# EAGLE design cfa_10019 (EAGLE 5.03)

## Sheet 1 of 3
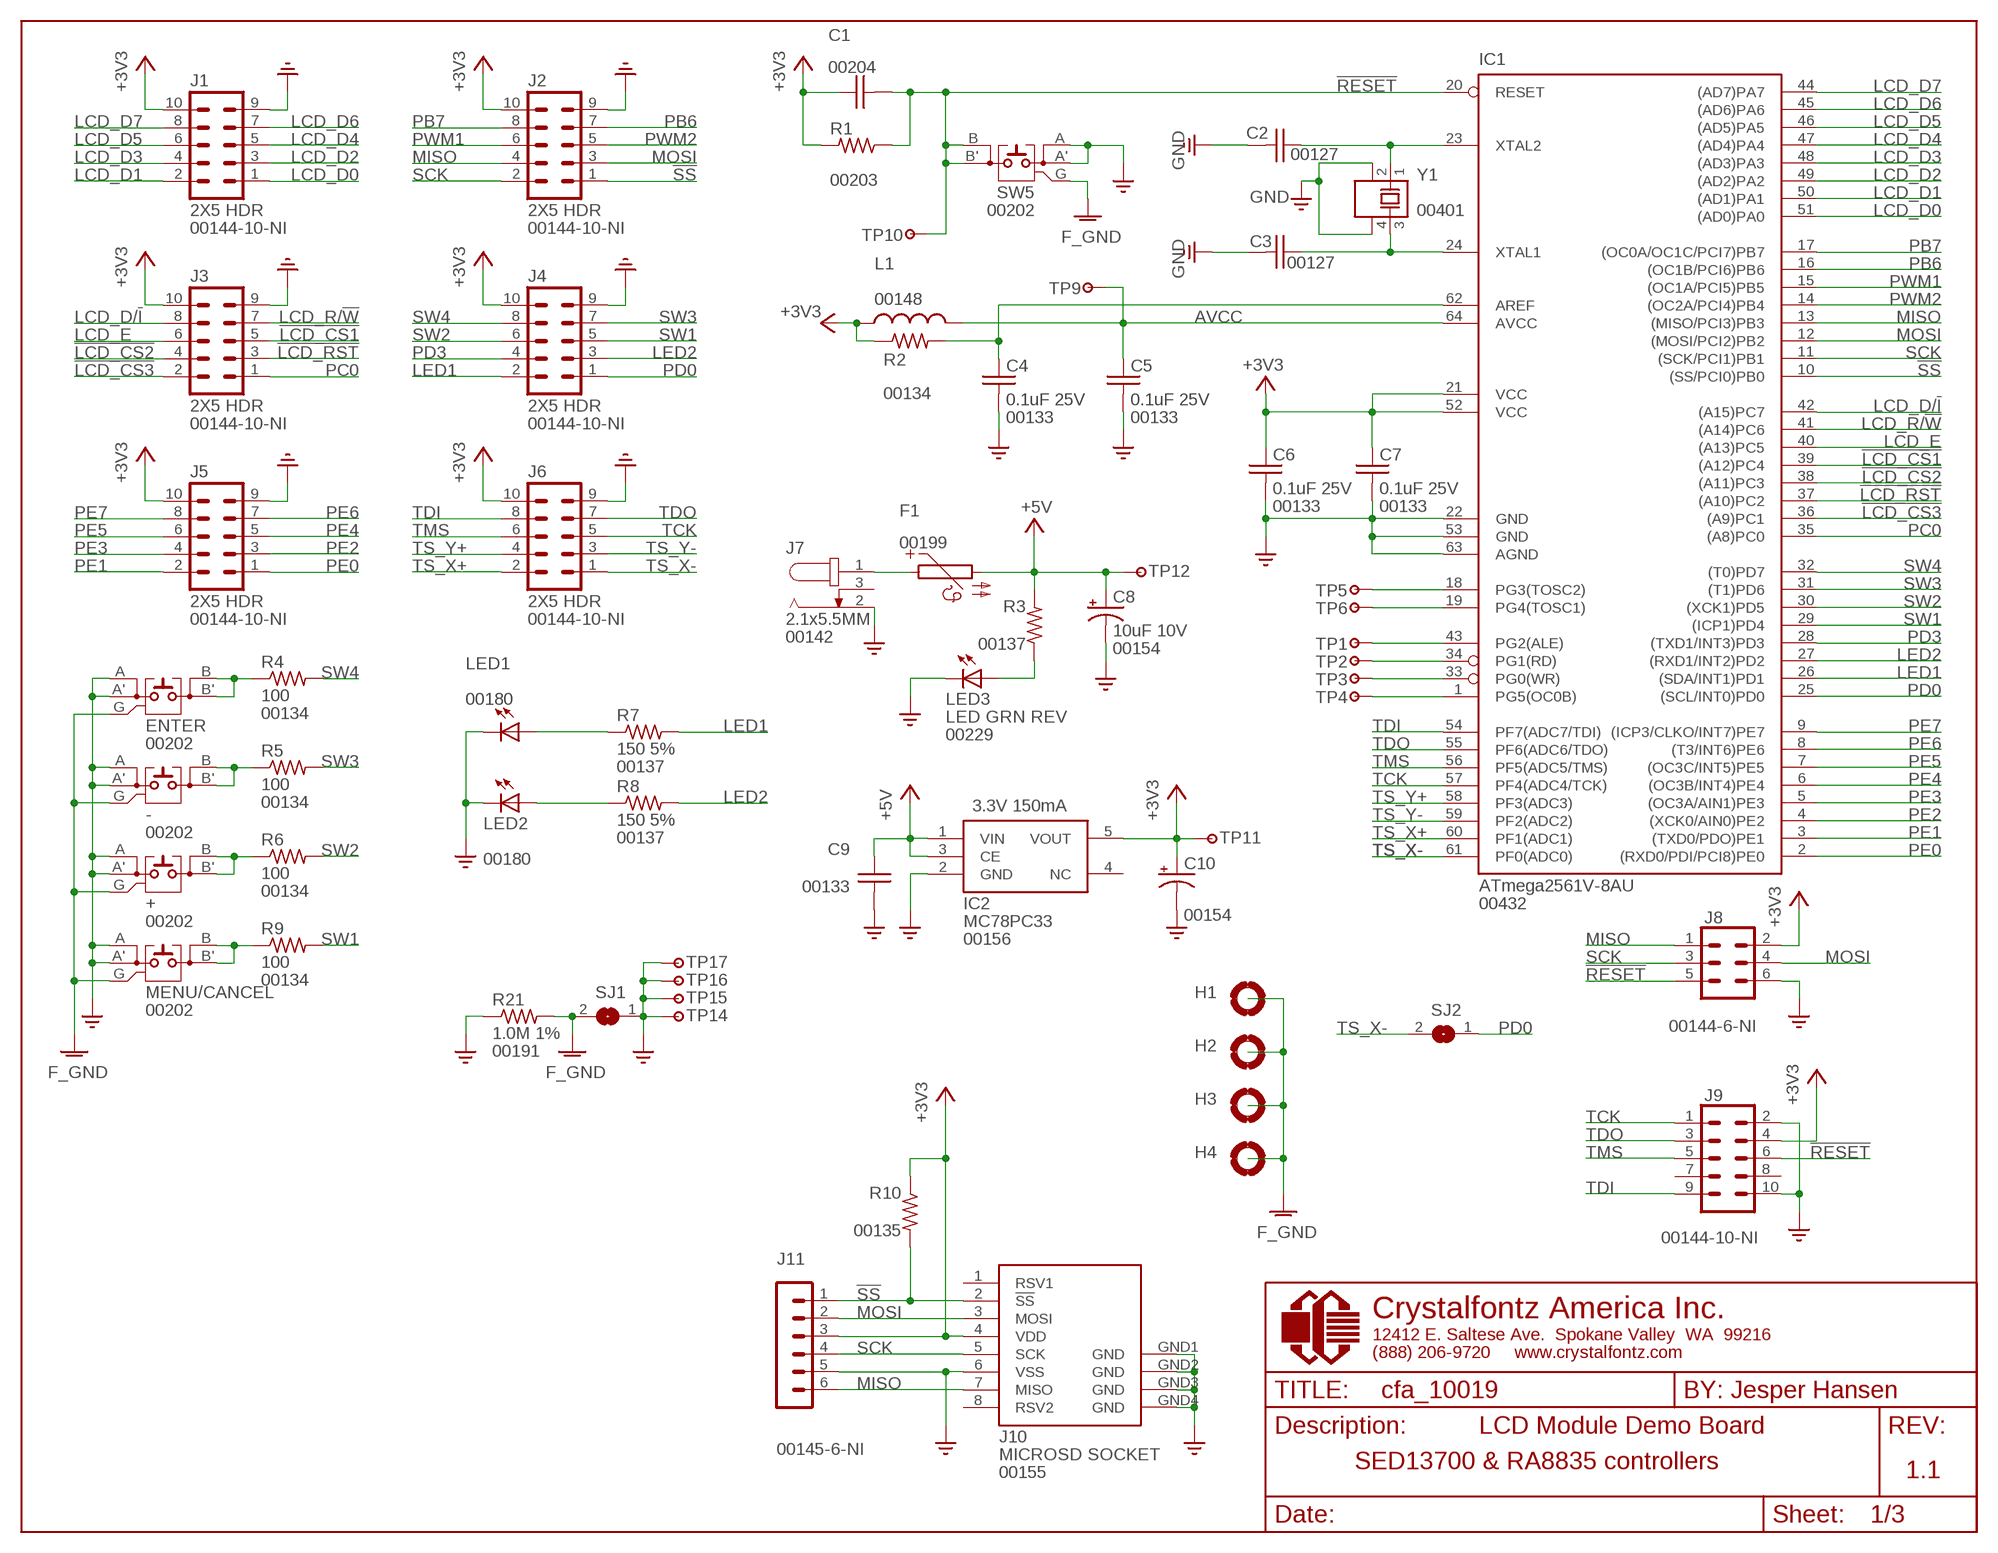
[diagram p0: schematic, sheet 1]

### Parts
+  00202  [EVQPB]
-  00202  [EVQPB]
C1  00204  [CAPC1608X90N]
C2  00127  [CAPC1608X87N]
C3  00127  [CAPC1608X87N]
C4  00133  [CAPC1608X87N]
C5  00133  [CAPC1608X87N]
C6  00133  [CAPC1608X87N]
C7  00133  [CAPC1608X87N]
C8  00154  [CAPMP6032X250N]
C9  00133  [CAPC1608X87N]
C10  00154  [CAPMP6032X250N]
ENTER  00202  [EVQPB]
F1  00199  [RESC3216X85N]
H1  MOUNT-PAD-ROUND3.2  [3,2-PAD]
H2  MOUNT-PAD-ROUND3.2  [3,2-PAD]
H3  MOUNT-PAD-ROUND3.2  [3,2-PAD]
H4  MOUNT-PAD-ROUND3.2  [3,2-PAD]
IC1  00432  [TQFP64-AEB]
IC2  00156  [SOT23-5L]
J1  00144-10-NI  [MA05-2]
J2  00144-10-NI  [MA05-2]
J3  00144-10-NI  [MA05-2]
J4  00144-10-NI  [MA05-2]
J5  00144-10-NI  [MA05-2]
J6  00144-10-NI  [MA05-2]
J7  00142  [PJ-102AH]
J8  00144-6-NI  [MA03-2]
J9  00144-10-NI  [MA05-2]
J10  00155  [3M_MICROSD]
J11  00145-6-NI  [MA06-1]
L1  00148  [R0805]
LED1  00180  [T776_LED_BOTTOM]
LED2  00180  [T776_LED_BOTTOM]
LED3  00229  [T776_LED_BOTTOM]
MENU/CANCEL  00202  [EVQPB]
R1  00203  [RESC1608X50N]
R2  00134  [RESC1608X38N]
R3  00137  [R0603]
R4  00134  [RESC1608X38N]
R5  00134  [RESC1608X38N]
R6  00134  [RESC1608X38N]
R7  00137  [R0603]
R8  00137  [R0603]
R9  00134  [RESC1608X38N]
R10  00135  [RESC1608X38N]
R21  00191  [RESC1608X55N]
SJ1  SJ  [SJ]
SJ2  SJ  [SJ]
SW5  00202  [EVQPB]
TP1  TP-VIA-3.2MM  [VIA-3.2MM-HOLE]
TP2  TP-VIA-3.2MM  [VIA-3.2MM-HOLE]
TP3  TP-VIA-3.2MM  [VIA-3.2MM-HOLE]
TP4  TP-VIA-3.2MM  [VIA-3.2MM-HOLE]
TP5  TP-VIA-3.2MM  [VIA-3.2MM-HOLE]
TP6  TP-VIA-3.2MM  [VIA-3.2MM-HOLE]
TP9  TP-VIA-1.0MM  [VIA-1MM-HOLE]
TP10  TP-VIA-1.0MM  [VIA-1MM-HOLE]
TP11  TP-VIA-1.0MM  [VIA-1MM-HOLE]
TP12  TP-VIA-1.0MM  [VIA-1MM-HOLE]
TP14  TP-VIA-1.0MM  [VIA-1MM-HOLE]
TP15  TP-VIA-1.0MM  [VIA-1MM-HOLE]
TP16  TP-VIA-1.0MM  [VIA-1MM-HOLE]
TP17  TP-VIA-1.0MM  [VIA-1MM-HOLE]
Y1  00401  [ABM3B]

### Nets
!LCD_CS1: IC1.39((A12)PC4) J3.5 ; also sheet 2
!LCD_CS2: IC1.38((A11)PC3) J3.4
!LCD_CS3: IC1.36((A9)PC1) J3.2
!LCD_RST: IC1.37((A10)PC2) J3.3 ; also sheet 2
!RESET: C1.2 IC1.20(RESET) J8.5 J9.6 R1.1 SW5.B SW5.B' TP10.1
!SS: IC1.10((SS/PCI0)PB0) J2.1 J10.2(!SS) J11.1 R10.2
+3V3: C1.1 C6.1 C7.1 C10.1(+) IC1.21(VCC) IC1.52(VCC) IC2.5(VOUT) J1.10 J2.10 J3.10 J4.10 J5.10 J6.10 J8.2 J9.4 J10.4(VDD) J11.3 L1.1 R1.2 R2.1 R10.1 TP11.1 ; also sheet 2
+5V: C8.1(+) C9.1 F1.2 IC2.1(VIN) IC2.3(CE) R3.2 TP12.1 ; also sheet 2
AVCC: C5.1 IC1.64(AVCC) L1.2 TP9.1
FOO: +.A +.A' -.A -.A' C2.2 C3.2 C4.2 C5.2 C6.2 C7.2 C8.2(-) C9.2 C10.2(-) ENTER.A ENTER.A' IC1.22(GND) IC1.53(GND) IC1.63(AGND) IC2.2(GND) J1.9 J2.9 J3.9 J4.9 J5.9 J6.9 J7.2 J8.6 J9.2 J9.10 J10.6(VSS) J10.GND1(GND) J10.GND2(GND) J10.GND3(GND) J10.GND4(GND) J11.5 LED1.K(C) LED2.K(C) LED3.K(C) MENU/CANCEL.A MENU/CANCEL.A' R21.1 SJ1.1 SW5.A SW5.A' TP14.1 TP15.1 TP16.1 TP17.1 Y1.2(GND) Y1.4(GND) ; supply symbol labelled GND ; also sheet 2
GNDA: +.G -.G ENTER.G H1.B3,2(MOUNT) H2.B3,2(MOUNT) H3.B3,2(MOUNT) H4.B3,2(MOUNT) MENU/CANCEL.G R21.2 SJ1.2 SW5.G ; supply symbol labelled F_GND
LCD_D0: IC1.51((AD0)PA0) J1.1 ; also sheet 2
LCD_D1: IC1.50((AD1)PA1) J1.2 ; also sheet 2
LCD_D2: IC1.49((AD2)PA2) J1.3 ; also sheet 2
LCD_D3: IC1.48((AD3)PA3) J1.4 ; also sheet 2
LCD_D4: IC1.47((AD4)PA4) J1.5 ; also sheet 2
LCD_D5: IC1.46((AD5)PA5) J1.6 ; also sheet 2
LCD_D6: IC1.45((AD6)PA6) J1.7 ; also sheet 2
LCD_D7: IC1.44((AD7)PA7) J1.8 ; also sheet 2
LCD_D/!I: IC1.42((A15)PC7) J3.8 ; also sheet 2
LCD_E: IC1.40((A13)PC5) J3.6 ; also sheet 2
LCD_R/!W: IC1.41((A14)PC6) J3.7 ; also sheet 2
LED1: IC1.26((SDA/INT1)PD1) J4.2 R7.2
LED2: IC1.27((RXD1/INT2)PD2) J4.3 R8.2
MISO: IC1.13((MISO/PCI3)PB3) J2.4 J8.1 J10.7(MISO) J11.6
MOSI: IC1.12((MOSI/PCI2)PB2) J2.3 J8.4 J10.3(MOSI) J11.2
N$1: C2.1 IC1.23(XTAL2) Y1.1
N$2: ENTER.B ENTER.B' R4.1
N$3: C3.1 IC1.24(XTAL1) Y1.3
N$4: -.B -.B' R5.1
N$5: IC1.19(PG4(TOSC1)) TP6.1
N$6: +.B +.B' R6.1
N$7: LED1.A R7.1
N$8: MENU/CANCEL.B MENU/CANCEL.B' R9.1
N$9: C4.1 IC1.62(AREF) R2.2
N$10: LED2.A R8.1
N$11: IC1.43(PG2(ALE)) TP1.1
N$13: IC1.34(PG1(RD)) TP2.1
N$14: F1.1 J7.1
N$15: IC1.33(PG0(WR)) TP3.1
N$17: LED3.A R3.1
N$18: IC1.18(PG3(TOSC2)) TP5.1
N$19: IC1.1(PG5(OC0B)) TP4.1
PB6: IC1.16((OC1B/PCI6)PB6) J2.7
PB7: IC1.17((OC0A/OC1C/PCI7)PB7) J2.8
PC0: IC1.35((A8)PC0) J3.1
PD0: IC1.25((SCL/INT0)PD0) J4.1 SJ2.1
PD3: IC1.28((TXD1/INT3)PD3) J4.4
PE0: IC1.2((RXD0/PDI/PCI8)PE0) J5.1
PE1: IC1.3((TXD0/PDO)PE1) J5.2
PE2: IC1.4((XCK0/AIN0)PE2) J5.3
PE3: IC1.5((OC3A/AIN1)PE3) J5.4
PE4: IC1.6((OC3B/INT4)PE4) J5.5
PE5: IC1.7((OC3C/INT5)PE5) J5.6
PE6: IC1.8((T3/INT6)PE6) J5.7
PE7: IC1.9((ICP3/CLKO/INT7)PE7) J5.8
PWM1: IC1.15((OC1A/PCI5)PB5) J2.6 ; also sheet 2
PWM2: IC1.14((OC2A/PCI4)PB4) J2.5 ; also sheet 2
SCK: IC1.11((SCK/PCI1)PB1) J2.2 J8.3 J10.5(SCK) J11.4
SW1: IC1.29((ICP1)PD4) J4.5 R9.2
SW2: IC1.30((XCK1)PD5) J4.6 R6.2
SW3: IC1.31((T1)PD6) J4.7 R5.2
SW4: IC1.32((T0)PD7) J4.8 R4.2
TCK: IC1.57(PF4(ADC4/TCK)) J6.5 J9.1
TDI: IC1.54(PF7(ADC7/TDI)) J6.8 J9.9
TDO: IC1.55(PF6(ADC6/TDO)) J6.7 J9.3
TMS: IC1.56(PF5(ADC5/TMS)) J6.6 J9.5
TS_X+: IC1.60(PF1(ADC1)) J6.2 ; also sheet 2
TS_X-: IC1.61(PF0(ADC0)) J6.1 SJ2.2 ; also sheet 2
TS_Y+: IC1.58(PF3(ADC3)) J6.4 ; also sheet 2
TS_Y-: IC1.59(PF2(ADC2)) J6.3 ; also sheet 2
Unconnected: IC2.4(NC) J7.3 J9.7 J9.8 J10.1(RSV1) J10.8(RSV2)

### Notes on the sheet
- 3.3V 150mA
- LCD Module Demo Board
- SED13700 & RA8835 controllers
- 1.1

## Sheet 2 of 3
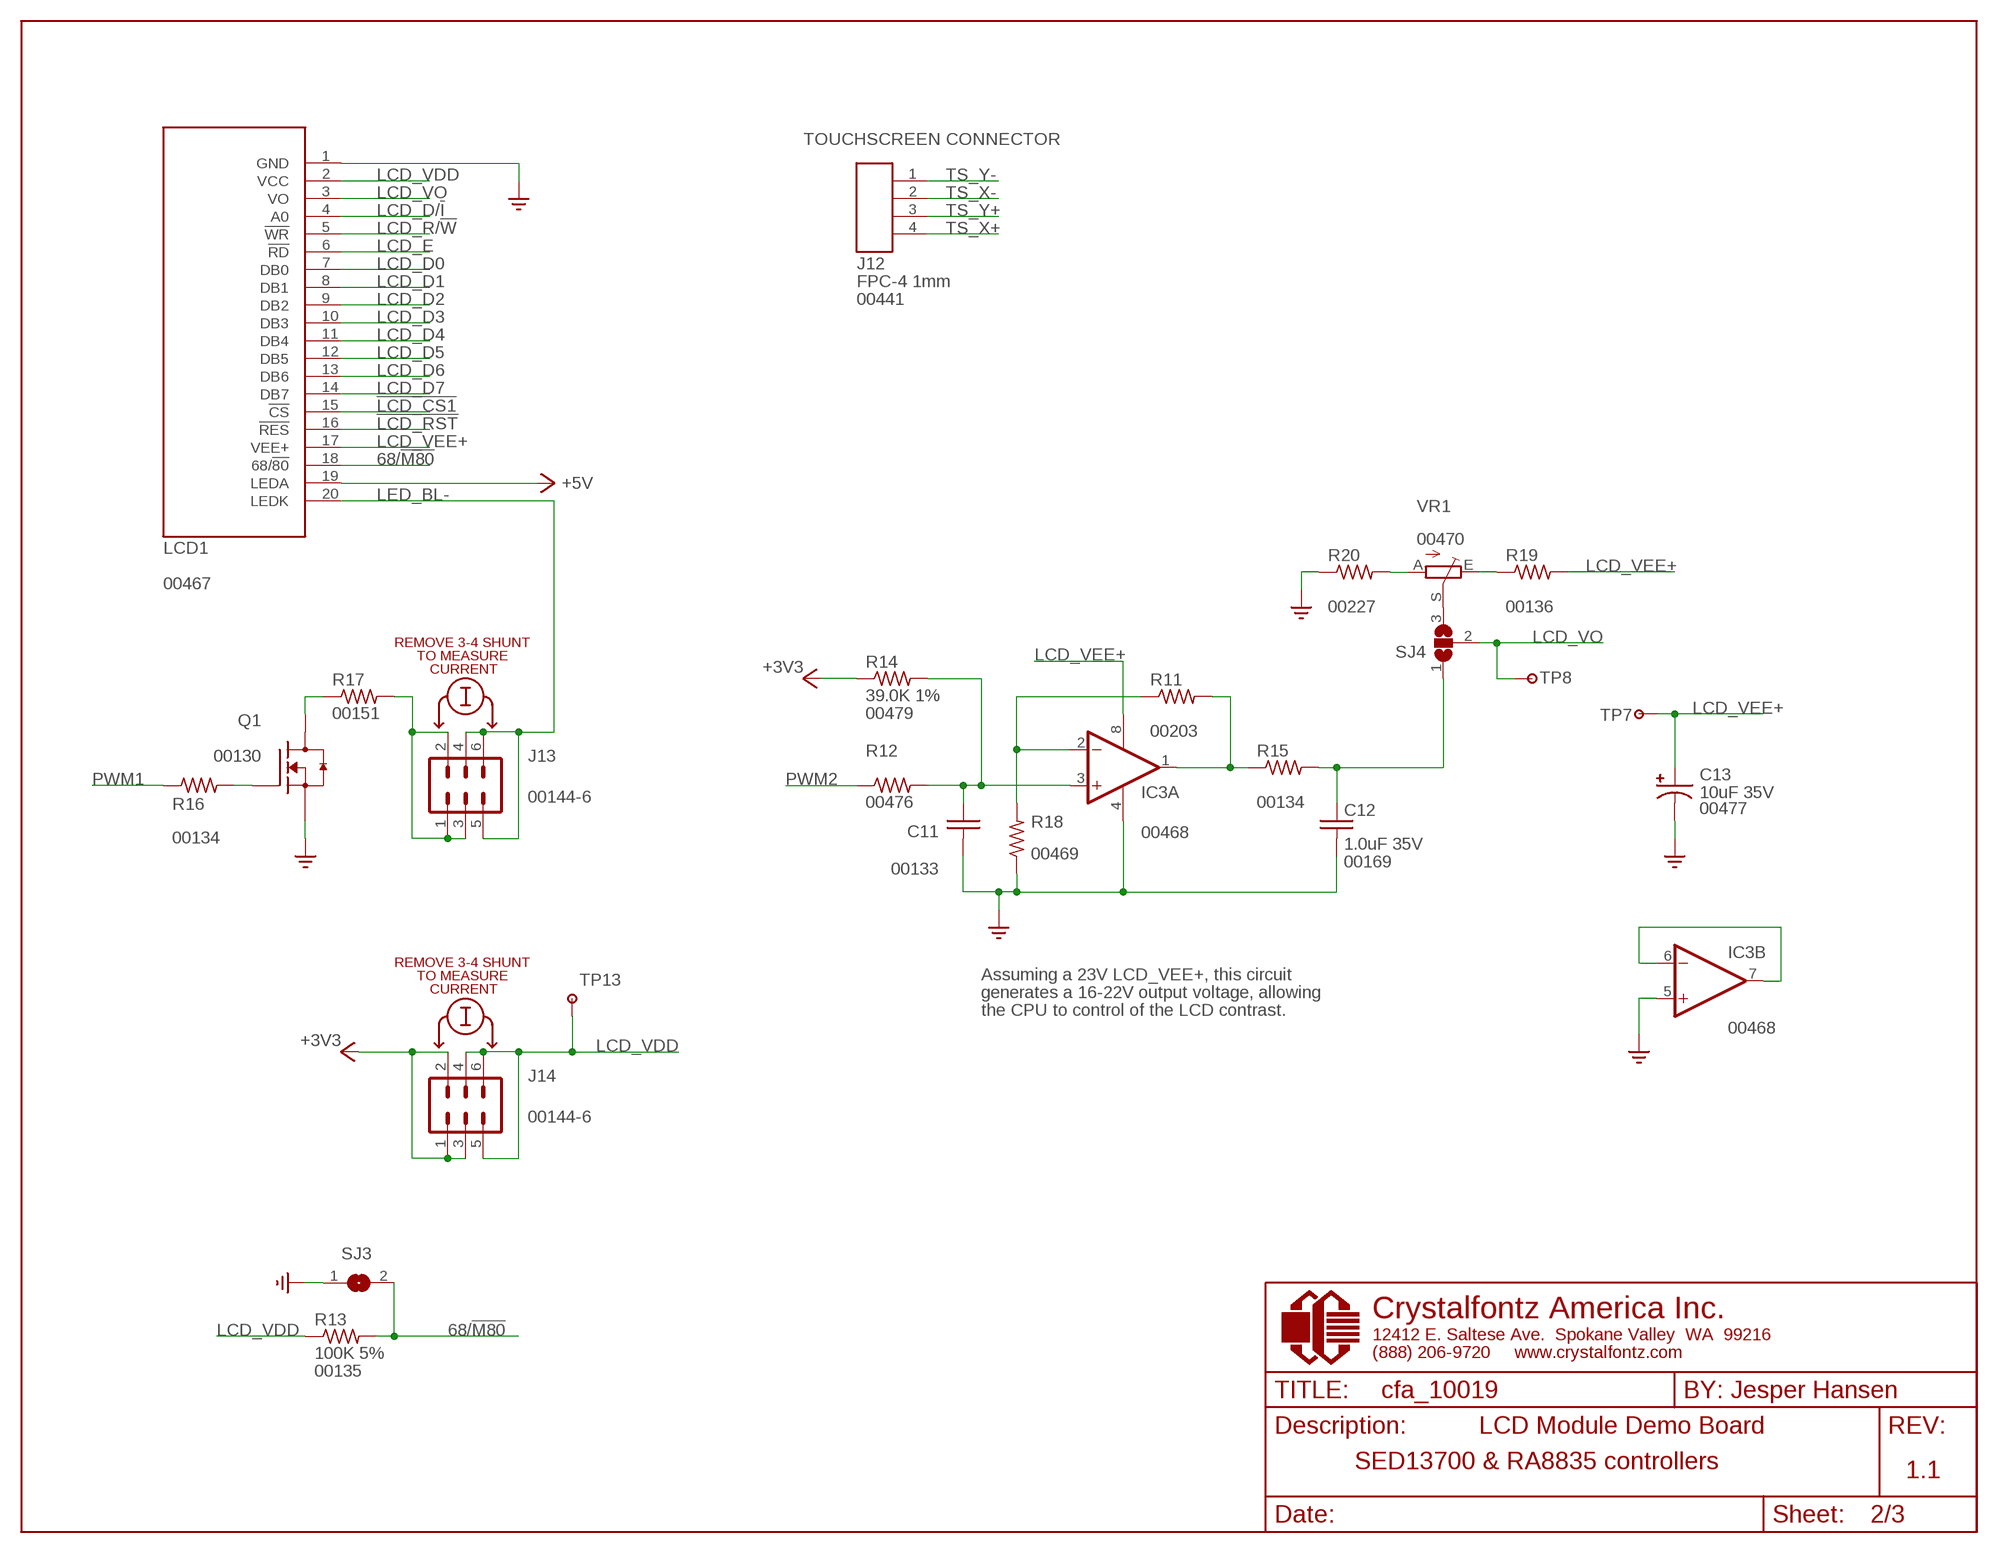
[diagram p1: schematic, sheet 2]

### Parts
C11  00133  [CAPC1608X87N]
C12  00169  [CAPC2012X125N]
C13  00477  [CAPMP6032X250N]
IC3  00468  [SO08]
J12  00441  [52207-0485]
J13  00144-6  [MA03-2]
J14  00144-6  [MA03-2]
LCD1  00467  [CFAX320240]
Q1  00130  [SOT23]
R11  00203  [RESC1608X50N]
R12  00476  [RESC1608X55N]
R13  00135  [RESC1608X38N]
R14  00479  [RESC1608X55N]
R15  00134  [RESC1608X38N]
R16  00134  [RESC1608X38N]
R17  00151  [R2010]
R18  00469  [RESC1608X55N]
R19  00136  [R0603]
R20  00227  [RESC1608X38N]
SJ3  SJ  [SJ]
SJ4  SJ2W  [SJ_2]
TP7  TP-VIA-1.0MM  [VIA-1MM-HOLE]
TP8  TP-VIA-1.0MM  [VIA-1MM-HOLE]
TP13  TP-VIA-1.0MM  [VIA-1MM-HOLE]
VR1  00470  [S63P]

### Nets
68/!M80: LCD1.18(68/!80) R13.2 SJ3.2
!LCD_CS1: LCD1.15(!CS) ; also sheet 1
!LCD_RST: LCD1.16(!RES) ; also sheet 1
+3V3: J14.1 J14.2 J14.3 R14.1 ; also sheet 1
+5V: LCD1.19(LEDA) ; also sheet 1
FOO: C11.2 C12.2 C13.2(-) IC3.4(A:V-) IC3.5(B:+IN) LCD1.1(GND) Q1.2(S) R18.1 R20.1 SJ3.1 ; supply symbol labelled GND ; also sheet 1
LCD_D0: LCD1.7(DB0) ; also sheet 1
LCD_D1: LCD1.8(DB1) ; also sheet 1
LCD_D2: LCD1.9(DB2) ; also sheet 1
LCD_D3: LCD1.10(DB3) ; also sheet 1
LCD_D4: LCD1.11(DB4) ; also sheet 1
LCD_D5: LCD1.12(DB5) ; also sheet 1
LCD_D6: LCD1.13(DB6) ; also sheet 1
LCD_D7: LCD1.14(DB7) ; also sheet 1
LCD_D/!I: LCD1.4(A0) ; also sheet 1
LCD_E: LCD1.6(!RD) ; also sheet 1
LCD_R/!W: LCD1.5(!WR) ; also sheet 1
LCD_VDD: J14.4 J14.5 J14.6 LCD1.2(VCC) R13.1 TP13.1
LCD_VEE+: C13.1(+) IC3.8(A:V+) LCD1.17(VEE+) R19.2 TP7.1
LCD_VO: LCD1.3(VO) SJ4.2 TP8.1
LED_BL-: J13.4 J13.5 J13.6 LCD1.20(LEDK)
N$12: IC3.2(A:-IN) R11.1 R18.2
N$16: IC3.1(A:OUT) R11.2 R15.1
N$20: IC3.6(B:-IN) IC3.7(B:OUT)
N$22: SJ4.3 VR1.S
N$23: C11.1 IC3.3(A:+IN) R12.2 R14.2
N$24: R20.2 VR1.A
N$25: J13.1 J13.2 J13.3 R17.2
N$26: R19.1 VR1.E
N$27: C12.1 R15.2 SJ4.1
N$30: Q1.3(D) R17.1
N$31: Q1.1(G) R16.2
PWM1: R16.1 ; also sheet 1
PWM2: R12.1 ; also sheet 1
TS_X+: J12.4 ; also sheet 1
TS_X-: J12.2 ; also sheet 1
TS_Y+: J12.3 ; also sheet 1
TS_Y-: J12.1 ; also sheet 1

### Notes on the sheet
- TOUCHSCREEN CONNECTOR
- REMOVE 3-4 SHUNT
- TO MEASURE
- CURRENT
- REMOVE 3-4 SHUNT
- TO MEASURE | Assuming a 23V LCD_VEE+, this circuit
- CURRENT
- generates a 16-22V output voltage, allowing
- the CPU to control of the LCD contrast.
- LCD Module Demo Board
- SED13700 & RA8835 controllers
- 1.1

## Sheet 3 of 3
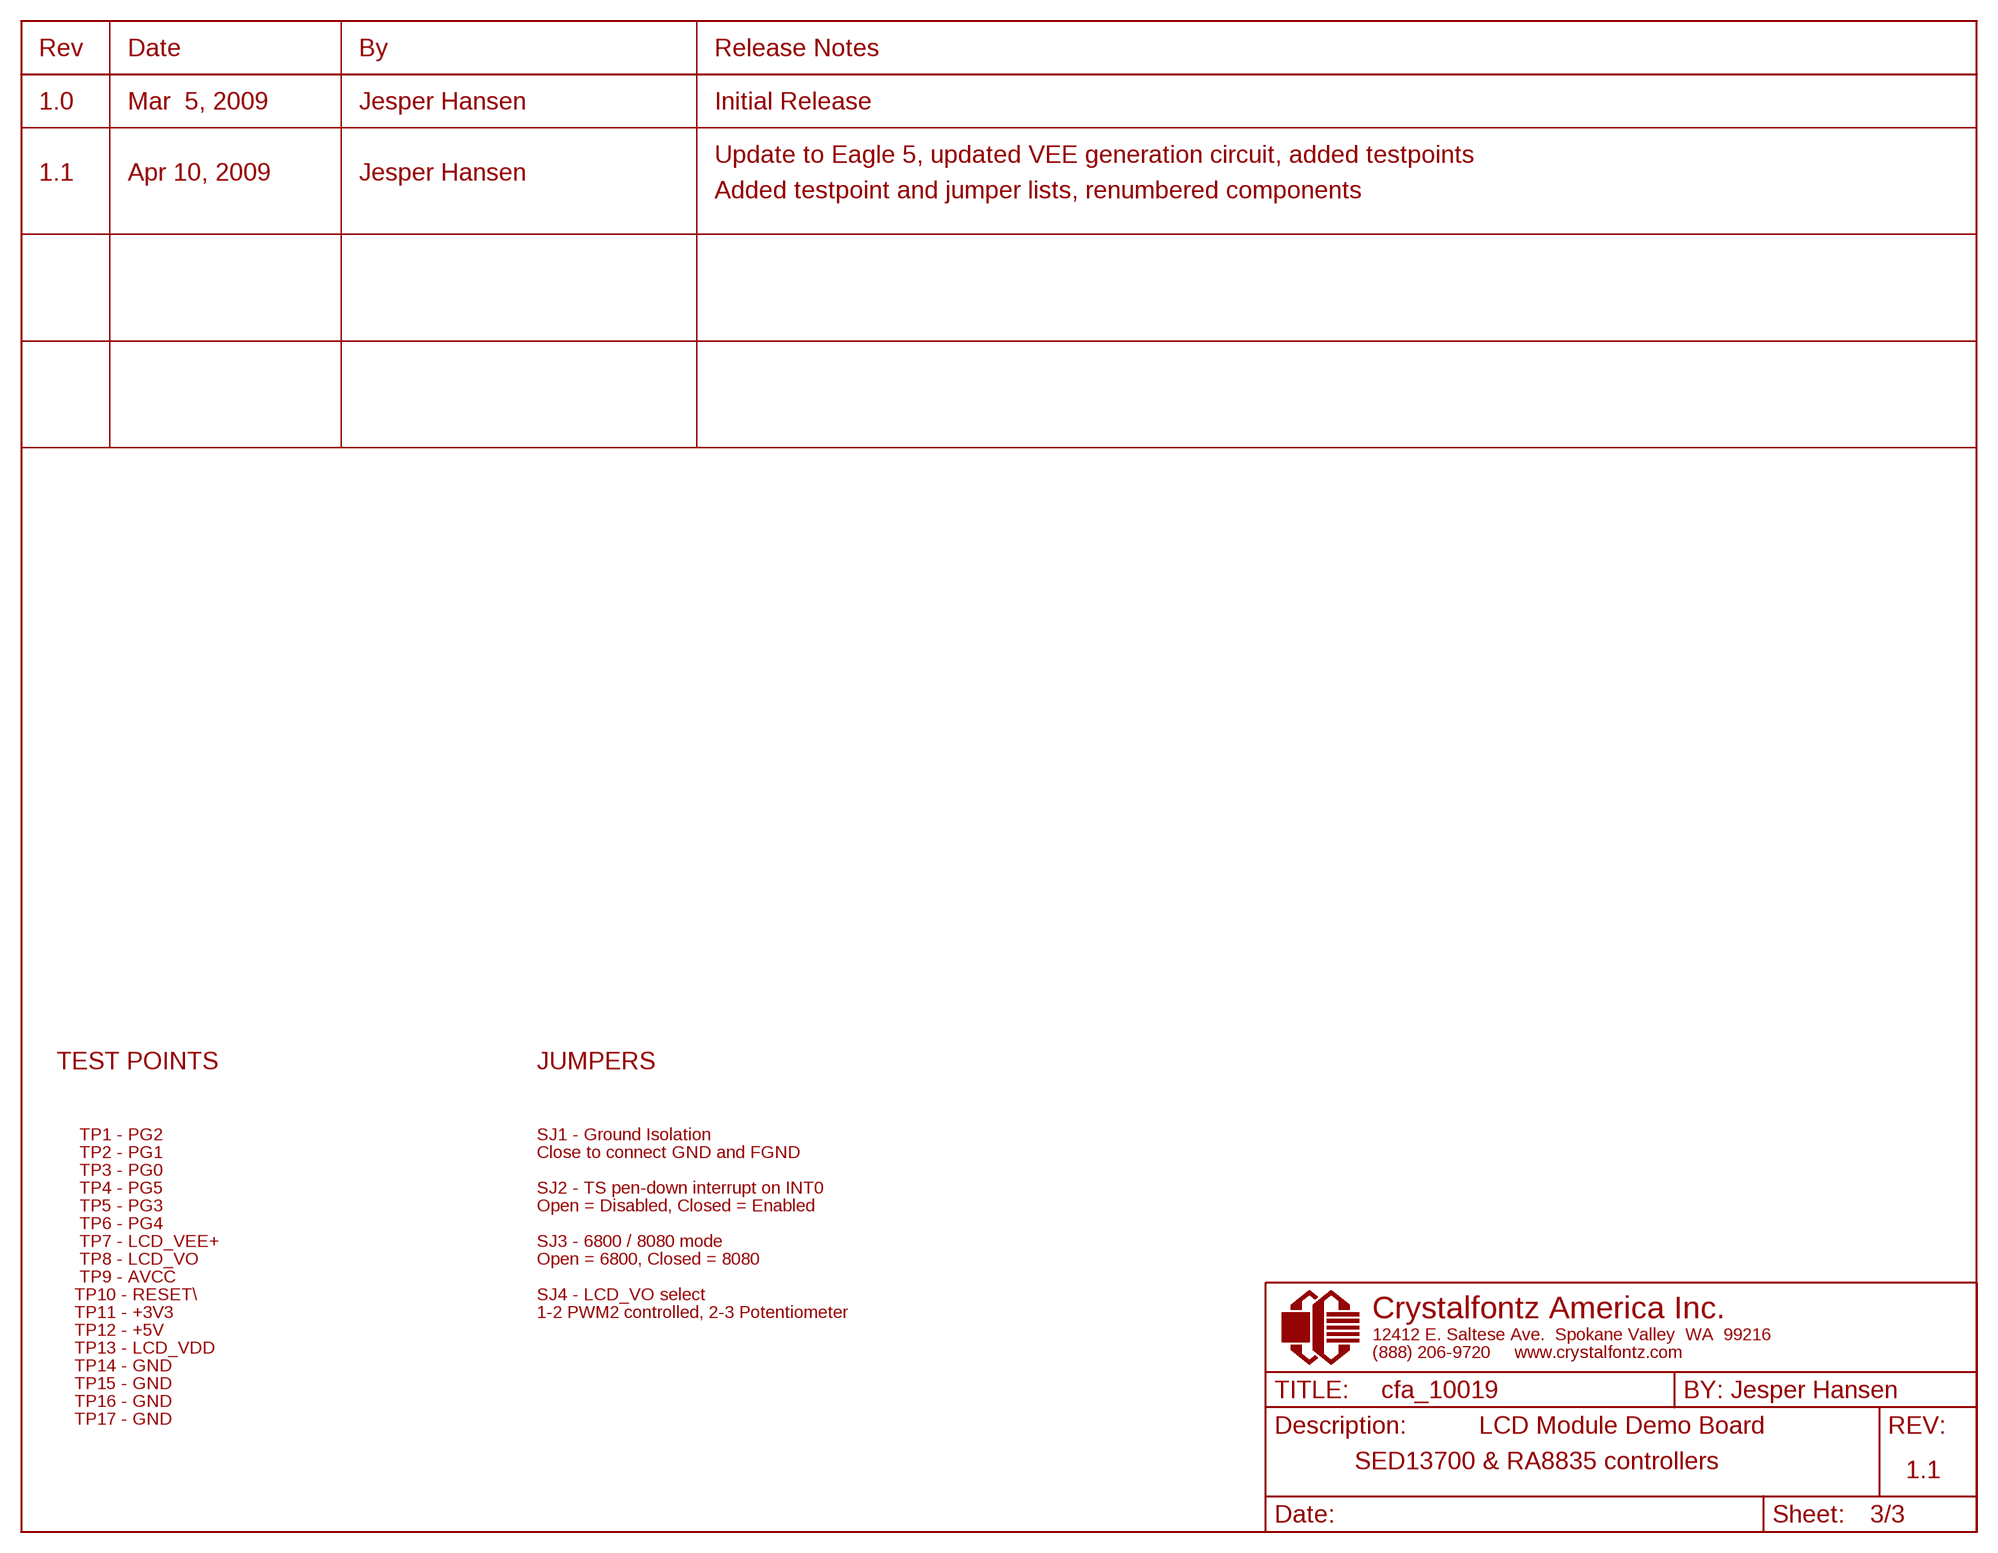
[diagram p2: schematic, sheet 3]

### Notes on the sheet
- Rev | Date | By | Release Notes
- 1.0 | Mar  5, 2009 | Jesper Hansen | Initial Release
- Update to Eagle 5, updated VEE generation circuit, added testpoints
- 1.1 | Apr 10, 2009 | Jesper Hansen
- Added testpoint and jumper lists, renumbered components
- TEST POINTS | JUMPERS
- TP1 - PG2 | SJ1 - Ground Isolation
- TP2 - PG1 | Close to connect GND and FGND
- TP3 - PG0
- TP4 - PG5 | SJ2 - TS pen-down interrupt on INT0
- TP5 - PG3 | Open = Disabled, Closed = Enabled
- TP6 - PG4
- TP7 - LCD_VEE+ | SJ3 - 6800 / 8080 mode
- TP8 - LCD_VO | Open = 6800, Closed = 8080
- TP9 - AVCC
- TP10 - RESET\\ | SJ4 - LCD_VO select
- TP11 - +3V3 | 1-2 PWM2 controlled, 2-3 Potentiometer
- TP12 - +5V
- TP13 - LCD_VDD
- TP14 - GND
- TP15 - GND
- TP16 - GND
- TP17 - GND
- LCD Module Demo Board
- SED13700 & RA8835 controllers
- 1.1

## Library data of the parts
+ - ENTER MENU/CANCEL SW5 = proddev_lib:00202: SPST MOM W/GND, 6MM LIGHT TOUCH SW W/GND H=7 TH; DESC: SPST MOM W/GND
C1 = proddev_lib:00204: 0.22uF 10V, CAP .22UF 10V CERAMIC X5R 0603; DESC: 0.22uF 10V
C2 C3 = proddev_lib:00127: 20pF, CAP CER 20PF 50V 5% C0G 0603; DESC: 20pF
C4-C7 C9 C11 = proddev_lib:00133: 0.1uF 25V, CAP .1UF 25V CERAMIC X7R 0603; DESC: 0.1uF 25V
C8 C10 = proddev_lib:00154: 10uF 10V, CAP TANT 10UF 10V 10% LOESR SMD; DESC: 10uF 10V
C12 = proddev_lib:00169: 1.0UF 35V, CAP CER 1.0UF 35V X7R 0805; DESC: 1.0uF 35V
C13 = proddev_lib2:00477: 10uF 35V,CAP TANTALUM 10UF 35V 20% SMD; DESC: 10uF 35V
F1 = proddev_lib:00199: 500mA, PTC RESETTABLE .50A 13.2V 1206; DESC: 500mA PTC
H1-H4 = holes:MOUNT-PAD-ROUND: MOUNTING PAD, round
IC1 = proddev_lib2:00432: ATmega2561V-8AU, IC AVR MCU 256K 8MHZ LOW-VOLTAGE 64TQFP 256 Kbytes FLASH 8 Kbytes SRAM 4 Kbytes EEPROM DUAL USART 8-channel 10 bit ADC; DESC: ATmega2561V-8AU
IC2 = proddev_lib:00156: MC78PC33, IC REG LDO 150MA 3.3V LN SOT23-5; DESC: MC78PC33
IC3 = proddev_lib2:00468: LT1490 Dual/Quad Over-The-Top Micropower Rail-to-Rail Input and Output Op Amps; DESC: LT1490
J1-J6 J9 = proddev_lib:00144-10-NI: 2X5 HDR, CONN HDR BRKWAY .100 VERT; DESC: 2X5 HDR
J7 = proddev_lib:00142: 2.1x5.5MM, CONN PWR JACK 2.1X5.5MM HIGH CUR; DESC: 2.1x5.5MM
J8 = proddev_lib:00144-6-NI: 2X3 HDR, CONN HDR BRKWAY .100 VERT; DESC: 2X3 HDR
J10 = proddev_lib:00155: MICROSD SOCKET, CONN EJECT MICROSD PUSH-PUSH SMD; DESC: MICROSD SOCKET
J11 = proddev_lib:00145-6-NI: 1X6 HDR, CONN HDR BRKWAY .100 VERT; DESC: 1X6 HDR
J12 = proddev_lib2:00441: CONN FFC/FPC 4POS 1MM R/A SMD, TOP CONTACTS; DESC: FPC-4 1mm
J13 J14 = proddev_lib:00144-6: 2X3 HDR, CONN HDR BRKWAY .100 VERT; DESC: 2X3 HDR
L1 = proddev_lib:00148: 10uH, FERRITE CHIP 1000 OHM 200MA 0805; DESC: 10uH FC
LCD1 = proddev_lib2:00467: Crystalfontz CFAX320240 series Size 95 x 70 mm; DESC: CFAX320240
LED1 LED2 = proddev_lib:00180: LST776, LED SUP RED REV GULWNG 645NM SMD; DESC: LST776 RED
LED3 = proddev_lib:00229: LED GRN, LED PURE GRN REV GLWNG 562NM SMD; DESC: LED GRN REV
Q1 = proddev_lib:00130: IRLML2402, MOSFET N-CH 20V 1.2A SOT-23; DESC: IRLML2402
R1 R11 = proddev_lib:00203: 47K 1/10W 5%, RES 47K OHM 1/10W 5% 0603 SMD; DESC: 47K 5%
R2 R4-R6 R9 R15 R16 = proddev_lib:00134: 100, RES 100 OHM 1/10W 5% 0603 SMD; DESC: 100
R3 R7 R8 = proddev_lib:00137: 150, RES 150 OHM 1/10W 5% 0603 SMD; DESC: 150 5%
R10 R13 = proddev_lib:00135: 100K, RES 100K OHM 1/10W 5% 0603 SMD; DESC: 100K 5%
R12 = proddev_lib2:00476: 15.0K 1/10W 1%,RES 15.0K OHM 1/10W 1% 0603 SMD; DESC: 15k 1%
R14 = proddev_lib2:00479: 39.0K 1%,RES 39.0K OHM 1/10W 1% 0603 SMD; DESC: 39.0K 1%
R17 = proddev_lib:00151: R 1/2W 2010, BACKLIGHT RES 1/2W 2010 SMD; DESC: R 1/2W 2010
R18 = proddev_lib2:00469: RES 8.20K OHM 1/10W 1% 0603 SMD; DESC: 8.2k 1%
R19 = proddev_lib:00136: 1K, RES 1.0K OHM 1/10W 5% 0603 SMD; DESC: 1K 5%
R20 = proddev_lib:00227: 22K, RES 22K OHM 1/10W 5% 0603 SMD; DESC: 22K 5%
R21 = proddev_lib:00191: 1.0M 1/10W 1%, RES 1.00M OHM 1/10W 1% 0603 SMD; DESC: 1.0M 1%
SJ1-SJ3 = proddev_lib:SJ: SMD solder JUMPER
SJ4 = proddev_lib:SJ2W: SMD solder JUMPER
TP1-TP6 = proddev_lib:TP-VIA-3.2MM: 3.2MM Hole Via TP
TP7-TP17 = proddev_lib:TP-VIA-1.0MM: TP 1MM HOLE
VR1 = proddev_lib2:00470: Single Turn Trimmer 3/8 SQ 10Kohms 10% Cermet; DESC: 10k 10%
Y1 = proddev_lib2:00401: Crystal; ABM3B Ceramic SMD Crystal, 5x3.2mm; DESC: 8MHz

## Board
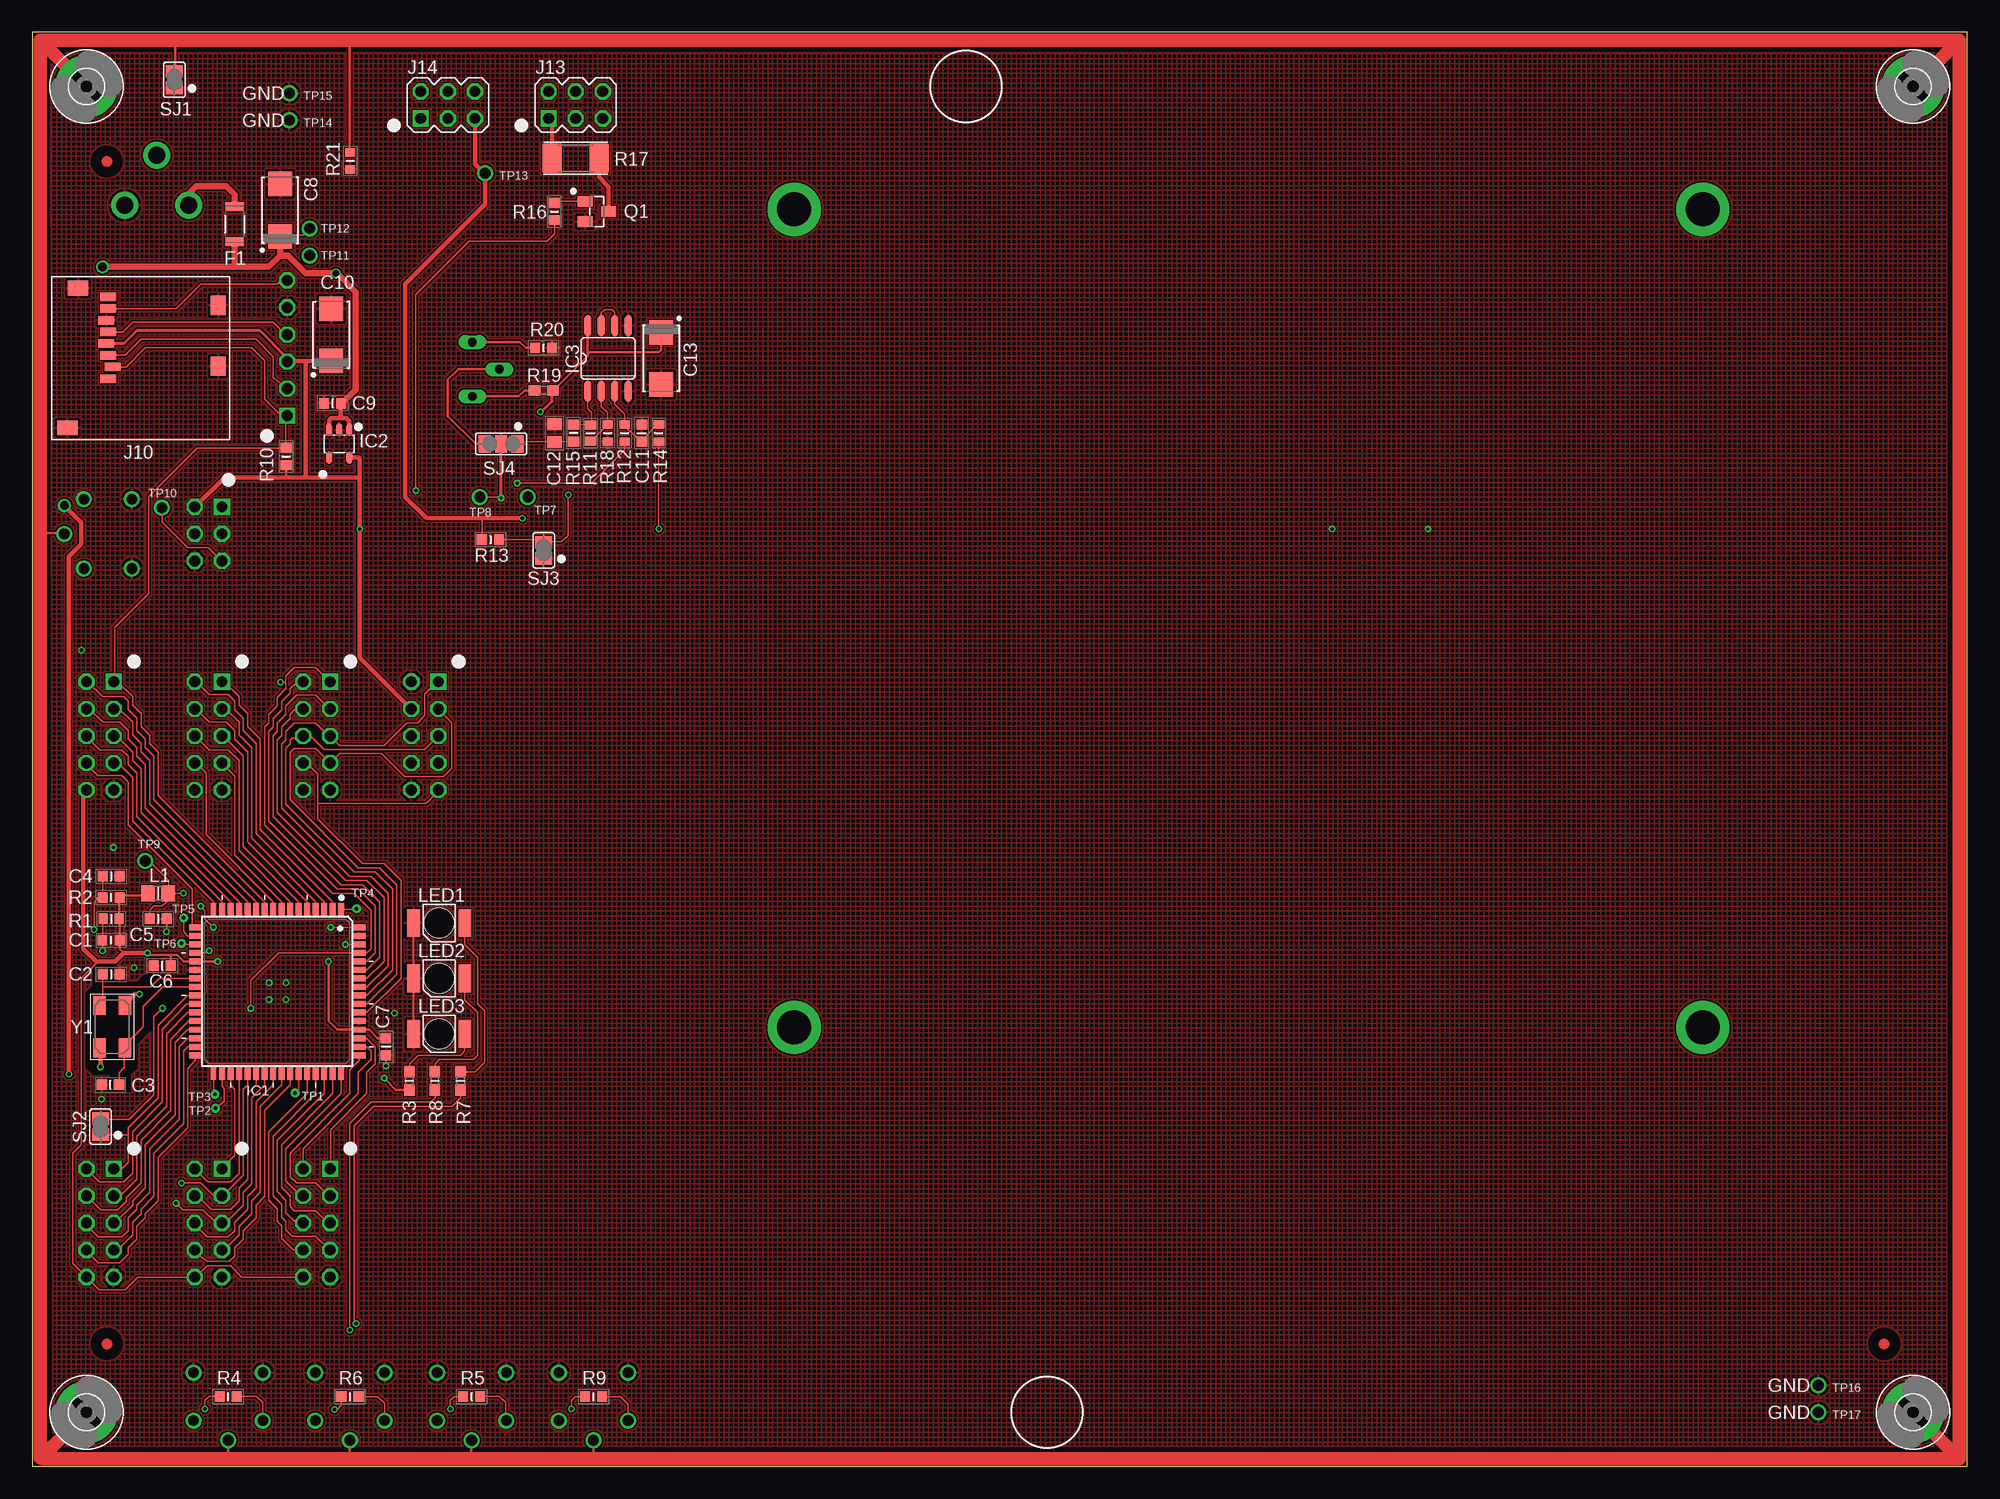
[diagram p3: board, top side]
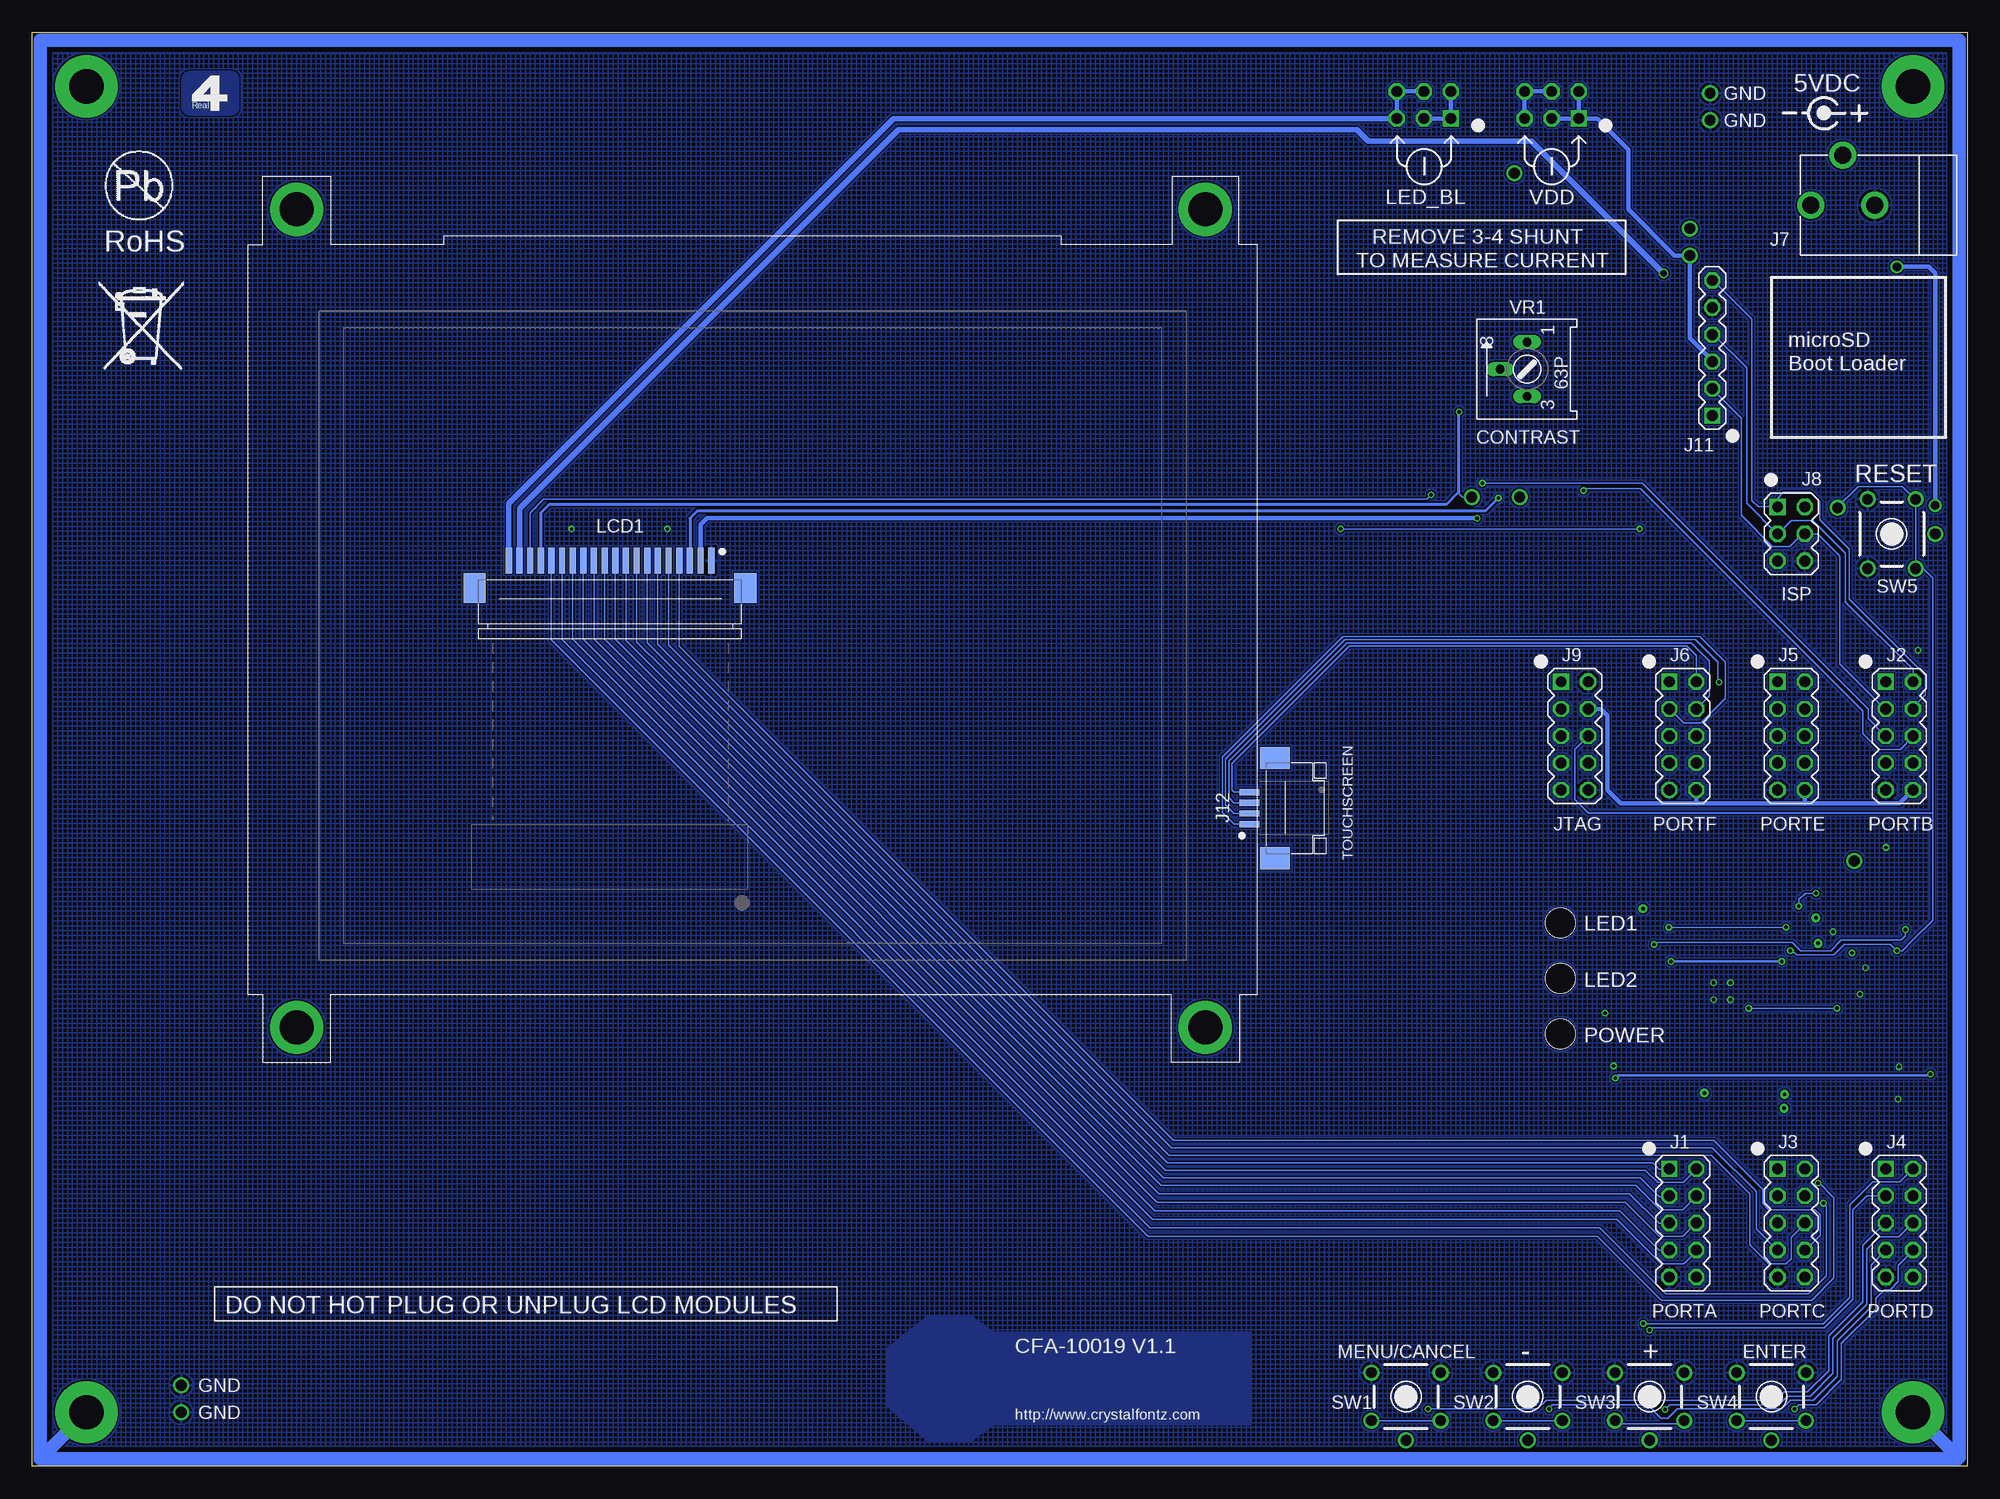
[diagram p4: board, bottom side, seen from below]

Size 181.61 x 134.62 mm. Coordinates in mm from the lower left corner, seen from the top.
Outline: 181.61,134.62 181.61,0 0,0 0,134.62 181.61,134.62
Outline: 181.61,134.62 181.61,134.62
Copper layers (1*2+15*16): Top 0.0254mm / dielectric 0.2032mm / Route2 0.0254mm / dielectric 1.4986mm / Route15 0.0254mm / dielectric 0.2032mm / Bottom 0.0254mm
Design rules "crystalfontz-2-layer": minimum track width 5mil, minimum drill 7mil, track to track 5mil, track to pad 5mil, pad to pad 5mil, via to via 5mil, smd to smd 5mil, copper to edge 5mil, drill to drill 10mil, minimum pad ring 10mil, minimum via ring 6mil, stop-mask expansion 0mil, vias tented up to drill 0mil, thermal gap 10mil
tRestrict: area 5.5,10 to 8.5,13; area 5.5,121 to 8.5,124; area 172.3,10 to 175.3,13; area 5.1,35.2 to 16.2,46.7

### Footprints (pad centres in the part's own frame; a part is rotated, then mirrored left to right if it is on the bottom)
EVQPB = drill 1 round: A -2.25,3.25; A' -2.25,-3.25; B 2.25,3.25; B' 2.25,-3.25; G 4.1,0
CAPC1608X90N = smd 0.9 x 0.95: 1 -0.8,0; 2 0.8,0
CAPC1608X87N = smd 0.95 x 1: 1 -0.8,0; 2 0.8,0
CAPMP6032X250N = smd 2.3 x 2.25: 1 -2.45,0; 2 2.45,0
CAPC2012X125N = smd 1.1 x 1.4: 1 -0.85,0; 2 0.85,0
RESC3216X85N = smd 0.85 x 1.8: 1 -1.65,0; 2 1.65,0
3,2-PAD = drill 3.2 pad 5.842 round: B3,2 0,0
TQFP64-AEB = smd 1.194 x 0.559: 1 -7.7,6; 2 -7.7,5.2; 3 -7.7,4.4; 4 -7.7,3.6; 5 -7.7,2.8; 6 -7.7,2; 7 -7.7,1.2; 8 -7.7,0.4; 9 -7.7,-0.4; 10 -7.7,-1.2; 11 -7.7,-2; 12 -7.7,-2.8; 13 -7.7,-3.6; 14 -7.7,-4.4; 15 -7.7,-5.2; 16 -7.7,-6; 33 7.7,-6; 34 7.7,-5.2; 35 7.7,-4.4; 36 7.7,-3.6; 37 7.7,-2.8; 38 7.7,-2; 39 7.7,-1.2; 40 7.7,-0.4; 41 7.7,0.4; 42 7.7,1.2; 43 7.7,2; 44 7.7,2.8; 45 7.7,3.6; 46 7.7,4.4; 47 7.7,5.2; 48 7.7,6 | smd 0.559 x 1.194: 17 -6,-7.7; 18 -5.2,-7.7; 19 -4.4,-7.7; 20 -3.6,-7.7; 21 -2.8,-7.7; 22 -2,-7.7; 23 -1.2,-7.7; 24 -0.4,-7.7; 25 0.4,-7.7; 26 1.2,-7.7; 27 2,-7.7; 28 2.8,-7.7; 29 3.6,-7.7; 30 4.4,-7.7; 31 5.2,-7.7; 32 6,-7.7; 49 6,7.7; 50 5.2,7.7; 51 4.4,7.7; 52 3.6,7.7; 53 2.8,7.7; 54 2,7.7; 55 1.2,7.7; 56 0.4,7.7; 57 -0.4,7.7; 58 -1.2,7.7; 59 -2,7.7; 60 -2.8,7.7; 61 -3.6,7.7; 62 -4.4,7.7; 63 -5.2,7.7; 64 -6,7.7
SOT23-5L = smd 0.55 x 1.2: 1 -0.95,-1.3; 2 0,-1.3; 3 0.95,-1.3; 4 0.95,1.3; 5 -0.95,1.3
SO08 = smd 0.66 x 2.032: 1 -1.905,-3.073; 2 -0.635,-3.073; 3 0.635,-3.073; 4 1.905,-3.073; 5 1.905,3.073; 6 0.635,3.073; 7 -0.635,3.073; 8 -1.905,3.073
MA05-2 = drill 1.016 square: 1 -5.08,-1.27 | drill 1.016 octagon: 2 -5.08,1.27; 3 -2.54,-1.27; 4 -2.54,1.27; 5 0,-1.27; 6 0,1.27; 7 2.54,-1.27; 8 2.54,1.27; 9 5.08,-1.27; 10 5.08,1.27
PJ-102AH = drill 1.6 pad 2.54 round: 1 -3,0; 2 3,0; 3 0,4.7
MA03-2 = drill 1.016 square: 1 -2.54,-1.27 | drill 1.016 octagon: 2 -2.54,1.27; 3 0,-1.27; 4 0,1.27; 5 2.54,-1.27; 6 2.54,1.27
3M_MICROSD = smd 0.8 x 1.5: 1 -6.89,10.3; 2 -5.79,9.9; 3 -4.69,10.3; 4 -3.59,10.5; 5 -2.49,10.3; 6 -1.39,10.5; 7 -0.29,10.3; 8 0.81,10.3 | smd 1.8 x 1.4: GND1 0,0; GND2 -5.7,0 | smd 1.4 x 1.9: GND3 -11.5,14.15; GND4 1.6,13.15
MA06-1 = drill 1.016 square: 1 -6.35,0 | drill 1.016 octagon: 2 -3.81,0; 3 -1.27,0; 4 1.27,0; 5 3.81,0; 6 6.35,0
52207-0485 = smd 0.6 x 1.9: 1 -1.5,0; 2 -0.5,0; 3 0.5,0; 4 1.5,0 | smd 2.1 x 2.8: P$1 -4.7,-2.4; P$2 4.7,-2.4
R0805 = smd 1.3 x 1.5: 1 -0.95,0; 2 0.95,0
CFAX320240 = smd 0.6 x 2.4: 1 3.88,-7.03; 2 4.88,-7.03; 3 5.88,-7.03; 4 6.88,-7.03; 5 7.88,-7.03; 6 8.88,-7.03; 7 9.88,-7.03; 8 10.88,-7.03; 9 11.88,-7.03; 10 12.88,-7.03; 11 13.88,-7.03; 12 14.88,-7.03; 13 15.88,-7.03; 14 16.88,-7.03; 15 17.88,-7.03; 16 18.88,-7.03; 17 19.88,-7.03; 18 20.88,-7.03; 19 21.88,-7.03; 20 22.88,-7.03 | drill 3.2 pad 5 round: P$1 42.8,36.8; P$2 42.8,-40; P$3 -42.5,-40; P$4 -42.5,36.8 | smd 2.1 x 2.8: P$5 26.09,-4.45; P$6 0.69,-4.45
T776_LED_BOTTOM = smd 1.2 x 2.6: A -2.4,0; K 2.4,0 | hole 2.8: 0,0
SOT23 = smd 1 x 1.4: 1 -0.95,-1.1; 2 0.95,-1.1; 3 0,1.1
RESC1608X50N = smd 0.85 x 1: 1 -0.75,0; 2 0.75,0
RESC1608X38N = smd 0.95 x 1: 1 -0.8,0; 2 0.8,0
R0603 = smd 1.1 x 1: 1 -0.85,0; 2 0.85,0
RESC1608X55N = smd 0.8 x 0.95: 1 -0.8,0; 2 0.8,0
R2010 = smd 1.8 x 2.7: 1 -2.2,0; 2 2.2,0
SJ = smd 1.168 x 1.6: 1 -0.762,0; 2 0.762,0
SJ_2 = smd 1.168 x 1.6: 1 -1.524,0; 2 0,0; 3 1.524,0
VIA-3.2MM-HOLE = drill 0.32 round: 1 0,0
VIA-1MM-HOLE = drill 1 round: 1 0,0
S63P = drill 0.813 long: A 2.54,0; E -2.54,0; S 0,2.54
ABM3B = smd 1.8 x 1.2: 1 -2,-1.2; 2 2,-1.2; 3 2,1.2; 4 -2,1.2

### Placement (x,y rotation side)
+  29.81,6.55 270 bottom
-  41.24,6.55 270 bottom
C1  7.4,49.4 180 top
C2  7.4,46.2 0 top
C3  7.33,35.83 180 top
C4  7.4,55.4 0 top
C5  11.8,51.4 0 top
C6  12.2,47 180 top
C7  33.2,39.4 270 top
C8  23.27,117.92 90 top
C9  28.2,99.8 180 top
C10  28.07,106.22 90 top
C11  57.2,97 90 top
C12  49,97 90 top
C13  59.01,104.02 270 top
ENTER  18.38,6.55 270 bottom
F1  19,116.6 270 top
H1  176.53,5.08 0 top
H2  176.53,129.54 0 top
H3  5.08,129.54 0 top
H4  5.08,5.08 0 top
IC1  23,44.6 270 top
IC2  28.8,96 180 top
IC3  54.03,104.01 0 top
J1  26.68,22.85 270 bottom
J2  6.36,68.57 270 bottom
J3  16.52,22.85 270 bottom
J4  6.36,22.85 270 bottom
J5  16.52,68.57 270 bottom
J6  26.68,68.57 270 bottom
J7  11.68,118.38 0 bottom
J8  16.52,87.54 270 bottom
J9  36.84,68.57 270 bottom
J10  17.44,108.99 90 top
J11  23.93,104.98 90 bottom
J12  67.37,61.8 90 bottom
J13  51,127.8 0 top
J14  39,127.8 0 top
L1  11.8,53.8 0 top
LCD1  114.01,78.01 180 bottom
LED1  38.2,51 180 top
LED2  38.2,45.8 180 top
LED3  38.2,40.6 180 top
MENU/CANCEL  52.67,6.55 270 bottom
Q1  53,117.8 270 top
R1  7.4,51.4 0 top
R2  7.4,53.4 180 top
R3  35.4,36.2 270 top
R4  18.38,6.55 180 top
R5  41.24,6.55 180 top
R6  29.81,6.55 180 top
R7  40.2,36.2 270 top
R8  37.8,36.2 270 top
R9  52.67,6.55 180 top
R10  23.82,94.81 90 top
R11  52.4,97 90 top
R12  55.6,97 90 top
R13  43,87 0 top
R14  58.8,97 90 top
R15  50.8,97 270 top
R16  49,117.8 90 top
R17  51,122.8 180 top
R18  54,97 90 top
R19  48,101 0 top
R20  48,105 180 top
R21  29.84,122.56 90 top
SJ1  13.34,130.18 90 top
SJ2  6.4,31.9 90 top
SJ3  48,86 90 top
SJ4  44,95.99 180 top
SW5  7.09,87.54 0 bottom
TP1  24.66,35.06 0 top
TP2  17.18,33.62 0 top
TP3  17.14,34.92 0 top
TP4  30.43,52.36 0 top
TP5  14.2,51.5 0 top
TP6  14,49.1 0 top
TP7  46.5,91 0 top
TP8  42,91 0 top
TP9  10.6,56.84 0 top
TP10  12.16,89.99 0 top
TP11  26.04,113.67 0 top
TP12  26.04,116.2 0 top
TP13  42.5,121.4 0 top
TP14  24.13,126.36 0 top
TP15  24.13,128.91 0 top
TP16  167.64,7.62 0 top
TP17  167.64,5.08 0 top
VR1  41.29,103 90 bottom
Y1  7.49,41.27 270 top

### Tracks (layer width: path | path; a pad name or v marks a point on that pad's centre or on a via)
68/!M80  (via drill 0.32)
  Top 0.152: v50.3,91.2 50.3,87.4 49.7,86.8 48.04,86.8 SJ3.2 47.76,87 R13.2
  Bottom 0.152: LCD1.18 134.89,89.51 133.6,90.8 50.7,90.8 v50.3,91.2
!LCD_CS1  (via drill 0.32)
  Top 0.152: IC1.39 21.8,35.8 20.6,34.6 20.6,26.53 19.8,25.73 19.8,24.53 18.2,22.93 17.85,22.93 J3.5 17.79,22.89 17.8,22.9 17.2,22.9 16,24.1 14.1,24.1 v13.5,24.7
  Bottom 0.152: LCD1.15 131.9,85.02 131.9,77.6 76.7,22.4 34.5,22.4 28.3,16.2 14.9,16.2 13.2,17.9 13.2,24.4 v13.5,24.7
!LCD_CS2
  Top 0.152: J3.4 15.5,25.4 16.77,24.13 18.6,24.13 19.4,24.93 19.4,26.13 20.2,26.93 20.2,35 21,35.8 IC1.38
!LCD_CS3
  Top 0.152: J3.2 16.45,26.73 18.6,26.73 19.4,27.53 IC1.36
!LCD_RST  (via drill 0.3)
  Top 0.152: IC1.37 20.2,35.8 19.8,35.4 19.8,27.33 18.43,25.96 18.34,25.96 J3.3 17.01,25.39 15.8,26.6 v14,26.6
  Bottom 0.152: LCD1.16 132.9,85.1 | LCD1.16 | v14,26.6 13.9,26.6 12.5,25.2 12.5,17.7 14.6,15.6 28.7,15.6 34.7,21.6 76.9,21.6 132.9,77.6 LCD1.16
!RESET  (via drill 0.32)
  Top 0.152: R1.1 6.6,51.4 C1.2 v6.6,48.4 | IC1.20 16.4,48.2 v16.6,48.4 | J8.5 17.79,84.97 17.78,84.96 16.51,86.23 14.61,86.23 12.2,88.64 12.2,89.91 12.16,89.95 TP10.1
  Bottom 0.152: v16.6,48.4 16.4,48.4 16,48 12.53,48 11.53,49 10.2,49 10,49 7.2,49 v6.6,48.4 6.11,48.4 5,49.51 5,49.5 3.23,51.27 3.23,61.34 | 3.23,61.34 3.23,83.4 4.12,84.29 SW5.B' 4.84,90.76 4.81,90.79 | 4.81,90.79 4.8,90.8 | 4.81,90.79 SW5.B 4.89,90.79 6.1,92 10.23,92 12.19,90.04 12.16,90.01 TP10.1 | J9.6 36.83,67.31 36.83,62.61 35.56,61.34 3.23,61.34
!SS
  Top 0.152: IC1.10 21.8,53 11.8,63 11.8,67.07 11,67.87 11,68.67 10.2,69.47 10.2,70.67 9.4,71.47 9.4,72.27 8.02,73.65 J2.1 7.63,73.67 7.75,73.79 7.75,78.74 10.92,81.92 10.92,91.06 15.47,95.61 R10.2 23.82,95.58 23.8,95.56 | J10.2 8.8,103.2 10.6,105 20.6,105 21.8,103.8 21.8,100.2 23.4,98.6 23.8,98.6 | 23.8,98.6 23.83,98.63 J11.1 | 23.8,95.56 23.8,98.6 | 23.8,95.56 23.75,95.5
+3V3  (via drill 0.3, 0.32)
  Top 0.152: 23.89,103.71 J11.3 | 15.27,17.77 16.4,18.85 18.6,18.85 19.63,17.77 25.39,17.77 J1.10 | 8.2,51.4 R1.2 | 8.15,53.35 R2.1 8.4,53.6 | L1.1 10.8,53.8 10.6,53.6 | 13,47.4 C6.1 | 6.2,47.4 4.6,45.8 4.6,30.2 3.8,29.4 3.8,19.06 J4.10 5.09,17.79 5.1,17.8 6.3,16.6 8.7,16.6 9.87,17.77 15.23,17.77 J3.10 | 30.6,41 IC1.52 | v58.8,88 R14.1
  Top 0.203: 23.83,103.77 23.8,103.8 | J3.10 15.27,17.77 | 6.2,47.4
  Top 0.254: 8.2,51.4 C1.1 8.25,49.4 | 8.4,53.6 10.6,53.6 | 13,48 11,48 v10.8,48.2 | 13,48 13.6,48 14.2,47.4 IC1.21 v17.4,47.4 | 13,48 13,47.4 | 8.6,48.2 8.2,48.6 8.2,49.35 8.25,49.4 | C7.1 32.4,40.2 31.6,41 30.6,41 28.6,41 27.8,41.8 v27.8,47.4 | R10.1 23.82,92.89 23.75,92.84 | 15.28,90.08 J8.2 | 8.25,49.4 8.26,49.4 | R2.1 8.19,53.4 8.13,53.34 8.15,53.32 R1.2
  Top 0.305: J10.4 8.6,105.4 9.8,106.6 21.4,106.6 23.8,104.2 23.8,103.8 23.89,103.71 | C10.1 28.18,103.77 28.19,103.76 | 30.73,94.64 30.69,94.7 | 25.65,92.84 25.68,92.86
  Top 0.406: v10.8,48.2 8.6,48.2 7.8,47.4 6.2,47.4 6,47.4 4.8,48.6 4.8,63.22 J2.10 | 25.68,103.77 23.83,103.77 | 25.68,103.77 C10.1 | 30.69,94.7 IC2.5 | 30.73,92.84 v30.73,88 30.73,75.95 J9.4 | 30.73,92.84 30.73,94.64 | 30.73,92.84 25.65,92.84 23.75,92.84 18.03,92.84 15.28,90.08 | 25.68,92.86 25.68,103.77
  Bottom 0.152: v30.73,88 v58.8,88
  Bottom 0.254: v17.4,47.4 v27.8,47.4 | 23.88,103.76 J11.3
  Bottom 0.406: J2.10 6.35,62.23 15.24,62.23 | 15.24,62.23 25.4,62.23 | 25.4,62.23 32.51,62.23 33.78,63.5 33.78,70.48 34.41,71.11 J9.4 | 15.24,62.23 15.24,62.36 15.25,62.37 J5.10 | 25.4,62.23 25.4,62.36 25.41,62.37 J6.10 | J9.4 | J9.4 | 23.88,103.76 26.04,105.92 TP11.1 27.46,113.67 31.8,118 31.8,123.6 34.7,126.5 36.3,126.5 36.33,126.53 J14.1 | 36.43,126.53 36.4,126.5 | J14.1 36.43,126.53 | 36.46,126.56 J14.2 36.5,129.1 | 36.43,126.53 36.46,126.56 | J14.3 36.53,126.53 36.5,126.5 | 36.46,126.56 36.5,126.6 | J14.1 36.46,126.56 | 36.5,126.5 J14.1 | 36.5,126.5 36.27,126.73
+5V  (via drill 0.32, 0.6, 0.8)
  Top 0.152: TP12.1 25.4,115.57 23.5,115.57
  Top 0.254: R3.2 34.12,35.35 v33.02,36.45
  Top 0.305: 23.26,115.34 23.2,115.4 C8.1 | C8.1 | 23.5,115.57 23.39,115.47 C8.1 | 28.96,99.69 29,99.74 C9.1 29.06,99.8
  Top 0.406: v3,90.2 4.6,88.6 4.6,86.6 3.4,85.4 3.4,36.86 v3.43,36.83 | IC2.1 29.75,98.14 29.46,98.42 28.96,98.42 | 28.96,99.69 28.96,98.42 | IC2.3 27.85,98.21 28.07,98.42 28.96,98.42 | 23.24,115.44 C8.1 23.27,115.43 23.3,115.4 | 18.92,112.6 18.92,112.65 19,112.73
  Top 0.508: 28.64,111.94 28.6,111.9 v28.5,112
  Top 0.61: v6.6,112.6 18.92,112.6 22.18,112.6 23.24,113.67 | 23.24,113.67 23.24,115.44 | 19,112.73 F1.2 | 29.06,99.8 30.35,101.09 30.35,110.24 28.64,111.94 28.57,112.01 25.65,112.01 24,113.67 23.24,113.67
  Bottom 0.254: 3.43,36.7 32.77,36.7 v33.02,36.45
  Bottom 0.406: v6.6,112.6 3.6,112.6 3,112 v3,90.2 | v3.43,36.83 3.43,36.7
  Bottom 0.508: LCD1.19 135.89,89.91 100.3,125.5 57.3,125.5 56.2,124.4 40.9,124.4 v28.5,112
AVCC  (via drill 0.32)
  Top 0.152: v17,50.6 16.2,51.4 16.2,52.2 v15.8,52.6 | C5.1 11,52.2 11.4,52.6 12.2,52.6 12.6,53 12.6,53.8 L1.2 12.8,53.8 | 12.8,53.8 v14.2,53.8 | TP9.1 10.96,56.84 12.8,55 12.8,53.8 | v28,50.6 IC1.64
  Bottom 0.152: v14.2,53.8 15.2,53.8 15.8,53.2 15.8,53.18 v15.8,52.6 | v17,50.6 v28,50.6
FOO  (via drill 0.3, 0.32)
  Top 0.152: v12.6,50.2 C5.2 | C2.2 | 17.4,109 17.41,108.99 J10.GND1 | 8.26,46.2 8.25,46.2 C2.2 | IC1.22 | IC1.63 | IC1.53
  Top 0.203: v33.2,37.6 C7.2 | LED1.K LED2.K LED3.K 35.8,41.4 35.4,41.8 | 30.6,41.8 | IC1.53 30.6,41.8 | J10.GND3 3.29,97.91
  Top 0.254: 28.13,108.67 28.2,108.6 | C10.2 28.13,108.67 | 28.13,108.67 28.01,108.79 | 17.4,109 17.41,108.99 J10.GND1
  Top 0.406: Y1.4 8.69,43.36 9.67,44.34 v10.06,44.34 | Y1.2 6.29,39.17 6.4,39.06 v6.4,37.51
  other vias: 23.81,45.4 7.62,58.1 6.5,34.48 22.23,45.4 4.6,76.6 9.53,46.83 22.23,43.81 23.81,43.81 33.97,42.55 122,88 131,88
  pour Bottom (rank 2, hatched): 1.91,132.72 179.71,132.72 179.71,1.91 1.91,1.91
  pour Top (rank 2, hatched): 1.71,132.72 179.71,132.72 179.71,1.91 1.91,1.91
GND1
  pour Bottom (rank 2): 101.35,5.84 101.35,10.92 97.54,13.97 93.47,13.97 91.44,12.45 67.31,12.45 67.31,4.06 91.44,4.06 93.47,2.54 97.54,2.54
GND2
  pour Bottom: 162.36,130.18 arc-90 163,130.81 166.79,130.81 arc-90 167.43,130.18 167.43,127.64 arc-90 166.79,127 163,127 arc-90 162.36,127.64
GNDA
  Top 0.203: 0.73,87.63 0.68,87.58 0.72,87.54 | 29.97,0.73 29.97,0.51 29.81,0.67 | 41.15,0.73 41.15,0.76 41.19,0.81 41.24,0.85
  Top 0.254: 13.4,134 13.4,133.88 13.4,131 SJ1.2 | R21.2 29.8,123.4 29.8,133.88 | 0.73,87.7 0.6,87.6 | 0.68,87.58 0.7,87.6 2.93,87.6 SW5.G | ENTER.G 18.4,2.43 18.4,0.73 | 29.81,0.67 29.8,0.68 +.G | 41.19,0.81 41.2,0.8 41.2,2.41 -.G | MENU/CANCEL.G 52.7,2.42 52.7,0.73 | H1.B3,2 | 134.4,133.88 134.4,133.9 134.35,133.85 | 140.7,0.73 140.6,0.8 140.55,0.85
  Top 0.406: SJ1.2 12.7,130.81
  Top 1.016: H3.B3,2 5.06,129.54 | H1.B3,2 | 180.88,133.88 180.79,133.8 180.8,133.8
  Top 1.27: 0.73,133.88 13.4,133.88 29.8,133.88 134.4,133.88 180.88,133.88 180.88,0.73 140.7,0.73 52.7,0.73 41.15,0.73 29.97,0.73 18.4,0.73 1.03,0.73 0.73,0.8 | 0.73,0.8 0.73,87.63 | 0.73,87.63 0.73,87.7 | 0.73,87.63 0.73,133.88 | 0.73,0.8 1.9,1.9 H4.B3,2 | H1.B3,2 180.7,0.9 | 180.79,133.8 H2.B3,2 | 0.73,133.88 H3.B3,2
  Bottom 1.016: H3.B3,2 5.06,129.54 | 180.88,0.73 180.78,0.82 | H1.B3,2
  Bottom 1.27: 0.73,0.9 0.86,0.73 180.88,0.73 180.88,133.88 0.73,133.88 0.73,0.9 | 0.73,0.9 0.8,0.8 H4.B3,2 | 180.78,0.82 H1.B3,2
LCD_D0
  Top 0.152: IC1.51 | IC1.51 | IC1.51 31.4,40.2 32.2,39.4 32.2,37.8 31.4,37 31.4,35 28,31.6 28,27.98 J1.1
  Bottom 0.152: J1.1 27.97,27.93 28,27.9 28.9,27.9 29.5,28.5 75.04,28.5 123.9,77.36 LCD1.7 | LCD1.7 123.9,85.1 | LCD1.7
LCD_D1
  Top 0.152: IC1.50 | IC1.50 | IC1.50 31.4,39.4 31.8,39 31.8,38.2 30.6,37 30.6,35 25.4,29.8 J1.2
  Bottom 0.152: J1.2 25.41,27.91 25.4,27.9 26.65,26.65 29.05,26.65 30.2,27.8 75.25,27.8 123.3,75.85 123.9,76.4 124.9,77.4 124.9,85.02 LCD1.8
LCD_D2
  Top 0.152: IC1.49 30.7,38.1 29.8,37.2 29.8,35 24.2,29.4 24.2,27.2 24.8,26.6 26.6,26.6 27.81,25.39 J1.3
  Bottom 0.152: J1.3 27.95,25.35 28,25.3 28.9,25.3 30.7,27.1 75.45,27.1 125.9,77.55 125.9,85.02 LCD1.9
LCD_D3
  Top 0.152: 29,35 IC1.48 | 29,35 29,35.8 | 29,35 23.8,29.8 23.8,26.8 25.21,25.39 J1.4
  Bottom 0.152: J1.4 26.7,24.1 28.8,24.1 31.1,26.4 75.65,26.4 126.9,77.65 126.9,85.02 LCD1.10
LCD_D4
  Top 0.152: 28.2,35 IC1.47 | 28.2,35 23.4,30.2 23.4,26.2 24.2,25.4 24.2,24.4 24.6,24 26.6,24 27.75,22.85 27.93,22.85 J1.5 | 28.2,35 28.2,35.4
  Bottom 0.152: J1.5 28,22.8 28.9,22.8 31.7,25.6 75.85,25.6 127.9,77.65 127.9,85.02 LCD1.11
LCD_D5
  Top 0.152: 27.4,35 IC1.46 | 27.4,35 27.4,35.8 | 27.4,35 23,30.6 23,25.8 23.8,25 23.8,23.8 24.75,22.85 25.39,22.85 J1.6
  Bottom 0.152: 25.41,22.89 25.4,22.9 | J1.6 25.41,22.89 | 25.41,22.89 26.7,21.6 28.9,21.6 32.1,24.8 76.05,24.8 128.9,77.65 128.9,85.02 LCD1.12
LCD_D6
  Top 0.152: 26.6,35 IC1.45 | 26.6,35 26.6,35.8 | 26.6,35 22.6,31 22.6,25.4 23.4,24.6 23.4,23.4 23.8,23 23.8,22.2 24.4,21.6 26.6,21.6 27.89,20.31 J1.7
  Bottom 0.152: J1.7 27.99,20.31 28,20.3 28.9,20.3 32.6,24 76.25,24 129.9,77.65 129.9,85.02 LCD1.13
LCD_D7
  Top 0.152: IC1.44 25.8,35.8 25.8,35 22.2,31.4 22.2,25 23,24.2 23,23 23.4,22.6 23.4,21.4 24.49,20.31 J1.8
  Bottom 0.152: J1.8 25.41,20.21 25.4,20.2 26.6,19 28.7,19 32.9,23.2 76.45,23.2 130.9,77.65 130.9,85.02 LCD1.14
LCD_D/!I
  Top 0.152: J3.8 15.2,20.26 15.2,20.13 16.4,19.23 18.5,19.23 19,19.73 19,20.53 19.8,21.33 19.8,22.13 21,23.33 21,24.53 21.8,25.33 21.8,33.4 24.2,35.8 IC1.42
  Bottom 0.152: J3.8 15.21,20.31 15.2,20.3 13.8,21.7 13.8,23.6 14.3,24.1 18.6,24.1 19.2,24.7 19.2,26 23.8,30.6 74.5,30.6 120.9,77 120.9,85.02 LCD1.4
LCD_E
  Top 0.152: 15.2,22.9 15.2,22.93 | J3.6 15.2,22.9 | 15.2,22.9 15.2,22.73 16.4,21.53 18.4,21.53 19,22.13 19,22.93 20.2,24.13 20.2,25.33 21,26.13 21,34.2 22.6,35.8 IC1.40
  Bottom 0.152: J3.6 15.2,22.8 16.5,21.5 16.5,19.5 17,19 18.6,19 20.4,20.8 20.4,25.6 24,29.2 74.9,29.2 122.9,77.2 LCD1.6 | LCD1.6 122.9,85.1 | LCD1.6
LCD_R/!W
  Top 0.152: J3.7 17.8,20.33 18,20.33 19.4,21.73 19.4,22.53 20.6,23.73 20.6,24.93 21.4,25.73 21.4,33.8 23.4,35.8 IC1.41
  Bottom 0.152: J3.7 19.8,22.3 19.8,25.8 23.9,29.9 74.7,29.9 121.9,77.1 121.9,85.02 LCD1.5
LCD_VDD  (via drill 0.32)
  Top 0.152: R13.1 42.2,88.9 42.3,89
  Top 0.406: J14.5 41.54,122.24 41.56,122.24 42.5,121.3 | 42.5,121.3 42.5,118.5 35,111 35,91 37,89 42.3,89 v46,89 | 42.5,121.3 TP13.1
  Bottom 0.406: J14.4 41.47,129.07 41.5,129.1 J14.6 41.54,126.66 41.6,126.6 J14.5 | LCD1.2 118.89,88.41 118.3,89 v46,89
LCD_VEE+  (via drill 0.32)
  Top 0.254: R19.2 48.9,101 52.12,104.22 52.12,104.6 | 52.12,104.6 IC3.8 | C13.1 59.01,104.81 58.8,104.6 52.12,104.6
  Top 0.305: v47.7,99 47.8,99 48.8,100 48.8,101 R19.2
  Bottom 0.152: TP7.1 47.4,91 47.8,91.4
  Bottom 0.305: LCD1.17 133.89,89.51 133.1,90.3 48.9,90.3 47.8,91.4 47.7,91.5 v47.7,99
LCD_VO  (via drill 0.32)
  Top 0.152: TP8.1 43.9,91 v44,90.9
  Top 0.305: v44,90.9 SJ4.2
  Bottom 0.305: LCD1.3 119.89,89.01 119.2,89.7 45.2,89.7 v44,90.9
LED1  (via drill 0.32)
  Top 0.152: IC1.26 14.5,43.4 12.2,41 12.2,34.2 9.4,31.4 9.4,27.93 | 9.4,27.93 9.4,27.73 | 9.4,27.93 9.4,27.53 8.6,26.73 6.29,26.73 J4.2 | R7.2 40.2,34.6 39.4,33.8 32.05,33.8 30.2,31.97 30.2,13.6 v30.4,13.4
  Bottom 0.152: v30.4,13.4 13.56,13.4 13.5,13.41 13.44,13.46 11.02,15.88 11.02,24.55 8.87,26.7 6.32,26.7 J4.2
LED2  (via drill 0.32)
  Top 0.152: IC1.27 | IC1.27 14.6,42.6 12.6,40.6 12.6,33.8 9.8,31 9.8,26.93 8.3,25.43 | 8.3,25.43 | J4.3 8.26,25.39 8.3,25.43 | v29.8,12.8 29.8,32.22 31.78,34.2 37.4,34.2 37.8,34.6 R8.2
  Bottom 0.152: J4.3 9.41,25.39 10.72,24.08 10.72,15.69 13.41,13 29.6,13 v29.8,12.8
LED_BL-
  Bottom 0.406: J13.4 53.43,129.07 53.5,129 53.54,129.04 J13.6 53.54,126.74 53.5,126.7 53.54,126.66 J13.5
  Bottom 0.508: J13.5 100.78,126.52 136.9,90.4 136.9,85.1 136.89,85.09 LCD1.20
  Bottom 0.61: J13.5
MISO
  Top 0.152: J2.4 5.36,71.11 6.6,69.87 8.2,69.87 9,69.07 9,68.27 9.8,67.47 9.8,66.67 10.6,65.87 10.6,61.8 19.4,53 IC1.13 | J10.7 13.5,108.7 15.8,111 23,111 23.33,111.33 J11.6
  Bottom 0.152: J2.4 5.2,71.11 5.21,71.12 3.94,72.39 3.94,74.3 11.05,81.41 11.05,86.11 13.84,88.9 13.84,90.55 14.73,91.44 17.27,91.44 17.79,90.92 J8.1 19.59,90.08 20.19,90.68 20.19,107.7 23.88,111.38 J11.6
MOSI
  Top 0.152: J2.3 8.16,71.11 9.4,69.87 9.4,68.67 10.2,67.87 10.2,67.07 11,66.27 11,62.2 20.2,53 IC1.12 | J10.3 8.7,104.3 10.2,105.8 21,105.8 22.6,104.2 22.6,102.2 23.97,101.17 | 23.97,101.17 24,101.2 | J11.2 23.97,101.17
  Bottom 0.152: J2.3 7.74,71.11 11.94,75.31 11.94,85.47 14.01,87.54 J8.4 15.46,87.54 16.64,86.36 18.29,86.36 21.21,89.28 21.21,98.42 23.95,101.17 | 23.95,101.17 24,101.22 | 23.95,101.17 J11.2
N$1
  Top 0.152: IC1.23 11.89,45.8 11.09,45 6.65,45 6.6,44.96 | 6.6,44.96 6.6,43.68 6.22,43.31 | 6.6,44.96 C2.1 | 6.22,43.31 6.2,43.28 | Y1.1 6.22,43.27 6.22,43.31
N$2
  Top 0.152: 21.6,4.4 21.63,4.37 ENTER.B' | 21.6,4.4 21.5,4.3 | 21.6,4.4 21.6,6 21,6.6 19.2,6.6 19.18,6.58 R4.1
  Bottom 0.152: 21.59,4.3 ENTER.B' | ENTER.B 21.59,4.3 | 21.59,4.3 21.59,4.29
N$3
  Top 0.152: IC1.24 12.23,45 10.41,43.18 10.41,41.27 8.69,39.55 Y1.3 8.69,39.31 8.64,39.37 8.64,37.47 8.13,36.96 C3.1
N$4
  Top 0.152: 44.43,4.4 44.49,4.34 -.B' | 44.43,4.4 44.33,4.3 | 44.43,4.4 44.43,6 43.83,6.6 42.03,6.6 42.04,6.59 R5.1
  Bottom 0.152: -.B' 44.5,4.32 | -.B' | -.B -.B'
N$5
  Top 0.152: IC1.19 14.2,49 TP6.1
N$6
  Top 0.152: 33.08,4.3 +.B' 33.06,5.93 32.44,6.55 30.73,6.55 30.72,6.57 30.7,6.55 R6.1
  Bottom 0.152: +.B 26.51,4.3 26.82,3.99 32.89,3.99 +.B'
N$7
  Top 0.152: R7.1 41.58,37.05 42.45,37.93 42.45,42.75 41.8,43.4 41.8,47.8 40.6,49 LED1.A
N$8
  Top 0.152: 55.94,4.3 MENU/CANCEL.B' 55.92,5.85 55.22,6.55 53.54,6.55 53.53,6.55 R9.1
  Bottom 0.152: 55.88,4.3 MENU/CANCEL.B' | MENU/CANCEL.B 55.88,4.3 | 55.88,4.3 55.88,4.29
N$9  (via drill 0.32)
  Top 0.152: v29.39,49 IC1.62 | v5.8,50.4 5.8,53 6.2,53.4 R2.2 C4.1
  Bottom 0.152: v5.8,50.4 5.8,49.8 6.2,49.4 9.6,49.4 9.8,49.4 11.8,49.4 12.8,48.4 15.6,48.4 16.4,49.2 29.19,49.2 v29.39,49
N$10
  Top 0.152: R8.1 37.8,37.8 38.2,38.2 41.4,38.2 41.8,38.6 41.8,42.6 40.6,43.8 LED2.A
N$11
  Top 0.152: TP1.1 25,35.4 IC1.43
N$12
  Top 0.152: IC3.2 53.4,99.5 54,98.9 54,97.9 R18.2 52.5,96.3 R11.1
N$13
  Top 0.152: IC1.34 17.8,35.74 18.02,35.42 18.02,34.26 TP2.1
N$14
  Top 0.61: J7.1 14.68,119.48 15.4,120.2 18.2,120.2 19,119.4 F1.1 19,118.2
N$15
  Top 0.152: IC1.33 17,35.07 TP3.1
N$16
  Top 0.152: IC3.1 52.12,99.28 52.5,98.9 52.5,97.8 | R11.2 52.5,97.8 | 52.5,97.8 R15.1
N$17
  Top 0.152: R3.1 35.4,37.8 36.2,38.6 40.2,38.6 40.6,39 LED3.A
N$18
  Top 0.152: IC1.18 14.55,49.8 14.2,50.2 TP5.1
N$19
  Top 0.152: 30.4,52.36 30.4,52.4 | 30.4,52.36 TP4.1 | IC1.1 30.4,52.3 30.4,52.36
N$20
  Top 0.152: IC3.6 54.66,108.33 54.4,108.6 53.7,108.6 53.4,108.3 53.4,107.1 53.4,107.09 IC3.7
N$22
  Top 0.254: VR1.S 40,103 39,102 39,98.6 41.6,96 42.5,96 SJ4.3
N$23
  Top 0.152: IC3.3 54.66,99.73 55.6,98.8 R12.2 55.5,97.7 C11.1 | 57.1,96.2 C11.1 | C11.1 57,96.2 57,96.3 | R14.2 58.5,97.7 C11.1
N$24
  Top 0.254: VR1.A 45.76,105.54 46.3,105 R20.2
N$25
  Top 0.406: J13.1 48.46,126.56 48.5,126.6 48.8,126.3 R17.2
  Bottom 0.406: J13.1 48.5,126.5 | J13.1 50.87,126.53 50.9,126.5 50.93,126.53 J13.3 | J13.2 J13.1
N$26
  Top 0.254: VR1.E 45.66,100.46 46.2,101 R19.1 47.2,101
N$27
  Top 0.152: 49.4,96.2 | 49.4,96.2 R15.2 | SJ4.1 45.5,96 45.7,96.2 49.25,96.2 C12.1 49.35,96.2 49.4,96.2
N$30
  Top 0.406: R17.1 53.2,121 54.1,120.1 Q1.3
N$31
  Top 0.152: R16.2 49.1,118.6 49.2,118.5 49.45,118.75 Q1.1
PB6
  Top 0.152: J2.7 8.04,66.03 9.4,64.67 9.4,60.6 17,53 IC1.16
PB7
  Top 0.152: IC1.17 | J2.8 5.09,65.91 6.13,64.87 8.4,64.87 9,64.27 9,60.2 15,54.2 15,50.79 15.19,50.6 IC1.17
PC0
  Top 0.152: J3.1 19,29.21 19,35.4 18.6,35.8 IC1.35
PD0
  Top 0.152: IC1.25 | IC1.25 14.6,44.2 11.8,41.4 11.8,34.6 9,31.8 9,31.14 | J4.1 8.4,27.93 9,28.53 9,31.14 | 9,31.14 8.97,31.14 SJ2.1
PD3
  Top 0.152: IC1.28 14.7,41.8 13,40.1 13,33.4 10.2,30.6 10.2,26.6 8.8,25.2 8.8,24.9 8,24.1 6.4,24.1 J4.4
PE0
  Top 0.152: J5.1 18.02,73.65 19.4,72.27 19.4,71.47 20.2,70.67 20.2,69.47 21.4,68.27 21.4,59.8 28.2,53 IC1.2
PE1
  Top 0.152: J5.2 15.42,73.65 16.6,72.47 18.4,72.47 19,71.87 19,71.07 19.8,70.27 19.8,69.07 21,67.87 21,59.4 27.4,53 IC1.3
PE2
  Top 0.152: J5.3 18.16,71.11 19.4,69.87 19.4,68.67 20.6,67.47 20.6,59 26.6,53 IC1.4
PE3
  Top 0.152: J5.4 15.36,71.11 16.6,69.87 18.2,69.87 19,69.07 19,68.27 20.2,67.07 20.2,58.6 25.8,53 IC1.5
PE4
  Top 0.152: J5.5 17.9,68.57 19.8,66.67 19.8,58.2 25,53 IC1.6
PE5
  Top 0.152: J5.6 15.3,68.57 16.6,67.27 18.4,67.27 19.4,66.27 19.4,57.8 24.2,53 IC1.7
PE6
  Top 0.152: IC1.8 23.4,53 19,57.4 19,64.8 17.79,66.01 J5.7
PE7
  Top 0.152: IC1.9 22.6,53 16.3,59.3 16.3,65.1 15.4,66 15.28,66 J5.8
PWM1  (via drill 0.32)
  Top 0.152: 17.8,52.2 IC1.15 17.8,53 9.8,61 9.8,65.07 9,65.87 9,66.67 8.4,67.27 6.33,67.27 5.09,68.51 J2.6 | v36,91.6 36,110 41,115 48.3,115 49,115.7 R16.1
  Bottom 0.152: v36,91.6 35.8,91.8 30.7,91.8 9.8,70.9 9.8,68.8 8.3,67.3 6.3,67.3 5.09,68.51 J2.6
PWM2  (via drill 0.32)
  Top 0.152: J2.5 7.9,68.57 9.4,67.07 9.4,66.27 10.2,65.47 10.2,61.4 18.6,53 IC1.14 | v45.5,92.3 52.5,92.3 55.6,95.4 R12.1
  Bottom 0.152: J2.5 7.67,68.57 9.3,70.2 9.3,71.1 30.5,92.3 v45.5,92.3
SCK
  Top 0.152: J2.2 5.22,73.65 6.6,72.27 8.6,72.27 9,71.87 9,71.07 9.8,70.27 9.8,69.07 10.6,68.27 10.6,67.47 11.4,66.67 11.4,62.6 21,53 IC1.11 | J10.5 8.5,106.5 9.4,107.4 22.6,107.4 23.75,106.25 J11.4
  Bottom 0.152: J2.2 5.09,73.78 5.08,74.8 11.43,81.15 11.43,85.72 14.48,88.77 16.51,88.77 17.74,87.54 J8.3 17.82,87.54 20.7,90.42 20.7,103.12 23.88,106.3 J11.4
SW1  (via drill 0.32)
  Top 0.152: IC1.29 | IC1.29 14.6,41 13.4,39.8 13.4,33 10.6,30.2 10.6,26.13 9.4,24.93 9.4,24.53 7.8,22.93 7.6,22.93 7.6,22.88 J4.5 | R9.2 50.95,6.55 50.6,6.2 v50.6,5.4
  Bottom 0.152: J4.5 7.62,22.86 | J4.5 | J4.5 7.65,22.84 7.84,22.71 9.8,20.75 9.8,15.47 13,12.27 13,9 15,7 17.15,7 17.93,6.22 28.71,6.22 38.73,6.22 39.5,6.22 40.32,5.4 v50.6,5.4
SW2  (via drill 0.32)
  Top 0.152: IC1.30 | IC1.30 14.6,40.2 13.8,39.4 13.8,32.6 11,29.8 11,25.73 9.8,24.53 9.8,24.13 9,23.33 9,22.13 8.4,21.53 6.2,21.53 5,22.73 5,22.76 J4.6 | v28.37,5.33 28.6,5.33 29,5.73 29,6.4 29.01,6.41 R6.2
  Bottom 0.152: J4.6 5.08,22.86 | J4.6 | J4.6 6.4,21.54 8.26,21.54 9.4,20.4 9.4,15.24 12.6,12.04 12.6,8.73 14.73,6.6 16.89,6.6 17.7,5.8 27.93,5.8 28.4,5.33 v28.37,5.33
SW3  (via drill 0.32)
  Top 0.152: IC1.31 | IC1.31 14.6,39.4 14.2,39 14.2,32.2 11.4,29.4 11.4,25.33 10.2,24.13 10.2,23.73 9.4,22.93 9.4,21.73 8,20.33 7.61,20.33 | 7.61,20.33 7.6,20.33 | J4.7 7.61,20.33 | R5.2 39.58,6.55 39.23,6.2 v39.23,5.4
  Bottom 0.152: J4.7 9,18.94 9,15 12.2,11.8 12.2,8.45 14.45,6.2 16.6,6.2 17.4,5.4 27.2,5.4 28.07,4.53 28.73,4.53 29.99,5.78 38.92,5.78 39.24,5.46 v39.23,5.4
SW4  (via drill 0.32)
  Top 0.152: IC1.32 15.3,38.1 14.6,37.3 14.6,31.8 | J4.8 5.07,20.33 5,20.33 6.2,19.13 8.2,19.13 9,19.93 9,20.53 9.8,21.33 9.8,22.53 10.6,23.33 10.6,23.73 11.8,24.93 11.8,29 14.6,31.8 | 14.6,31.8 | R4.2 17.53,6.6 16.6,6.6 16.2,6.2 v16.2,5.4
  Bottom 0.152: v16.2,5.4 15.8,5.8 14.18,5.8 11.8,8.18 11.8,11.04 11.81,11.05 11.81,11.56 8.6,14.77 8.6,15.8 7.8,16.6 7.21,16.6 6.45,17.36 6.46,18.87 5.01,20.31 | 5.01,20.31 4.99,20.33 | 5.01,20.31 J4.8
TCK
  Top 0.152: IC1.57 31.4,45 33.4,47 33.4,53.8 31.8,55.4 29.8,55.4 23.4,61.8 23.4,67.8 23.8,68.2 23.8,69 24.6,69.8 26.6,69.8 27.83,68.57 J6.5 28.83,67.69 33.02,67.69 33.9,68.57 33.91,68.57 33.91,68.58 35.13,69.8 36.15,69.8 36.83,70.48 36.83,72.52 37.97,73.66 37.98,73.65 J9.1
TDI
  Top 0.152: IC1.54 31.4,42.6 34.6,45.8 34.6,55 33,56.6 31,56.6 26.8,60.8 26.8,62.23 | J6.8 25.77,66.03 26.8,65 26.8,62.23 | J9.9 38.11,63.38 36.96,62.23 26.8,62.23 | 26.8,62.23
TDO
  Top 0.152: IC1.55 31.4,43.4 34.2,46.2 34.2,54.6 32.6,56.2 30.6,56.2 24.2,62.6 24.2,67 24.6,67.4 26.6,67.4 27.95,66.05 J6.7 27.81,65.91 28.83,66.93 32.77,66.93 34.92,64.77 38.61,64.77 39.37,65.53 39.37,69.85 J9.3
TMS
  Top 0.152: IC1.56 31.4,44.2 33.8,46.6 33.8,54.2 32.2,55.8 30.2,55.8 23.8,62.2 23.8,67.4 24.2,67.8 24.2,68.2 24.4,68.4 25.2,68.4 25.4,68.6 25.41,68.59 J6.6 26.13,68.57 27.4,67.3 36.82,67.3 J9.5 38.11,68.59
TS_X+
  Top 0.152: IC1.60 31.4,47.4 32.2,48.2 32.2,52.6 30.6,54.2 28.6,54.2 22.2,60.6 22.2,69 22.6,69.4 22.6,70.2 23.4,71 23.4,71.8 24.2,72.6 24.2,73 24.8,73.6 25.4,73.6 25.41,73.61 J6.2
  Bottom 0.152: J6.2 25.41,73.61 25.4,73.6 25.4,76.1 26.3,77 58,77 69,66 69,63.5 68.8,63.3 67.4,63.3 J12.4
TS_X-  (via drill 0.32)
  Top 0.152: 23.8,73.6 23.8,73 23,72.2 23,71.4 22.2,70.6 22.2,69.8 21.8,69.4 21.8,60.2 28.2,53.8 30.2,53.8 31.8,52.2 31.8,48.6 31.4,48.2 IC1.61 23.1,48.2 20.5,45.6 v20.5,43 | 23.8,73.6 23.8,74.2 24.6,75 26.6,75 J6.1 | 23.8,73.6 v23.3,73.6 | v12.2,43 11.4,42.2 11.4,34.9 9.1,32.6 6.3,32.6 6.36,32.66 SJ2.2
  Bottom 0.152: v23.3,73.6 23.4,73.8 23.4,75.5 25.5,77.6 58.4,77.6 69.6,66.4 69.6,62.1 68.8,61.3 67.5,61.3 J12.2 | v12.2,43 v20.5,43
TS_Y+
  Top 0.152: IC1.58 31.4,45.8 33,47.4 33,53.4 31.4,55 29.4,55 23,61.4 23,68.2 23.4,68.6 23.4,69.4 24.2,70.2 24.2,70.6 24.6,71 25.4,71 25.41,71.01 J6.4
  Bottom 0.152: J6.4 24.2,72.3 24.2,75.6 25.9,77.3 58.2,77.3 69.3,66.2 69.3,62.8 68.8,62.3 67.4,62.3 J12.3
TS_Y-
  Top 0.152: IC1.59 31.4,46.6 32.6,47.8 32.6,53 31,54.6 29,54.6 22.6,61 22.6,68.6 23,69 23,69.8 23.8,70.6 23.8,71.4 24.8,72.4 26.6,72.4 27.89,71.11 J6.3
  Bottom 0.152: J6.3 27.91,71.11 26.6,69.8 25,69.8 22.7,72.1 22.7,75.5 25.1,77.9 58.6,77.9 69.9,66.6 69.9,61.4 68.8,60.3 67.4,60.3 J12.1
(copper drawn outside any net)
  shapes: Top circle x3

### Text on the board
tPlace: GND | GND | GND | GND
bPlace: 5VDC | GND | l | a | e | R | GND | I | I | VDD | LED_BL | REMOVE 3-4 SHUNT | RoHS | TO MEASURE CURRENT | microSD | Boot Loader | CONTRAST | RESET | ISP | PORTB | PORTE | PORTF | JTAG | TOUCHSCREEN | LED1 | LED2 | POWER | PORTD | PORTC | PORTA | DO NOT HOT PLUG OR UNPLUG LCD MODULES | CFA-10019 V1.1 | GND | SW4 | SW3 | SW2 | SW1 | http://www.crystalfontz.com | GND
